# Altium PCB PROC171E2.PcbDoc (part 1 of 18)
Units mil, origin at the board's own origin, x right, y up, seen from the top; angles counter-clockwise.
Board outline 7700 x 2300 mil, 6 copper layers (Top Layer, GND 1, SIG 1, SIG 2, GND 2, Bottom Layer), stack 61.062 mil thick; 937 components, 687 nets, 11931 pads, 1719 vias.
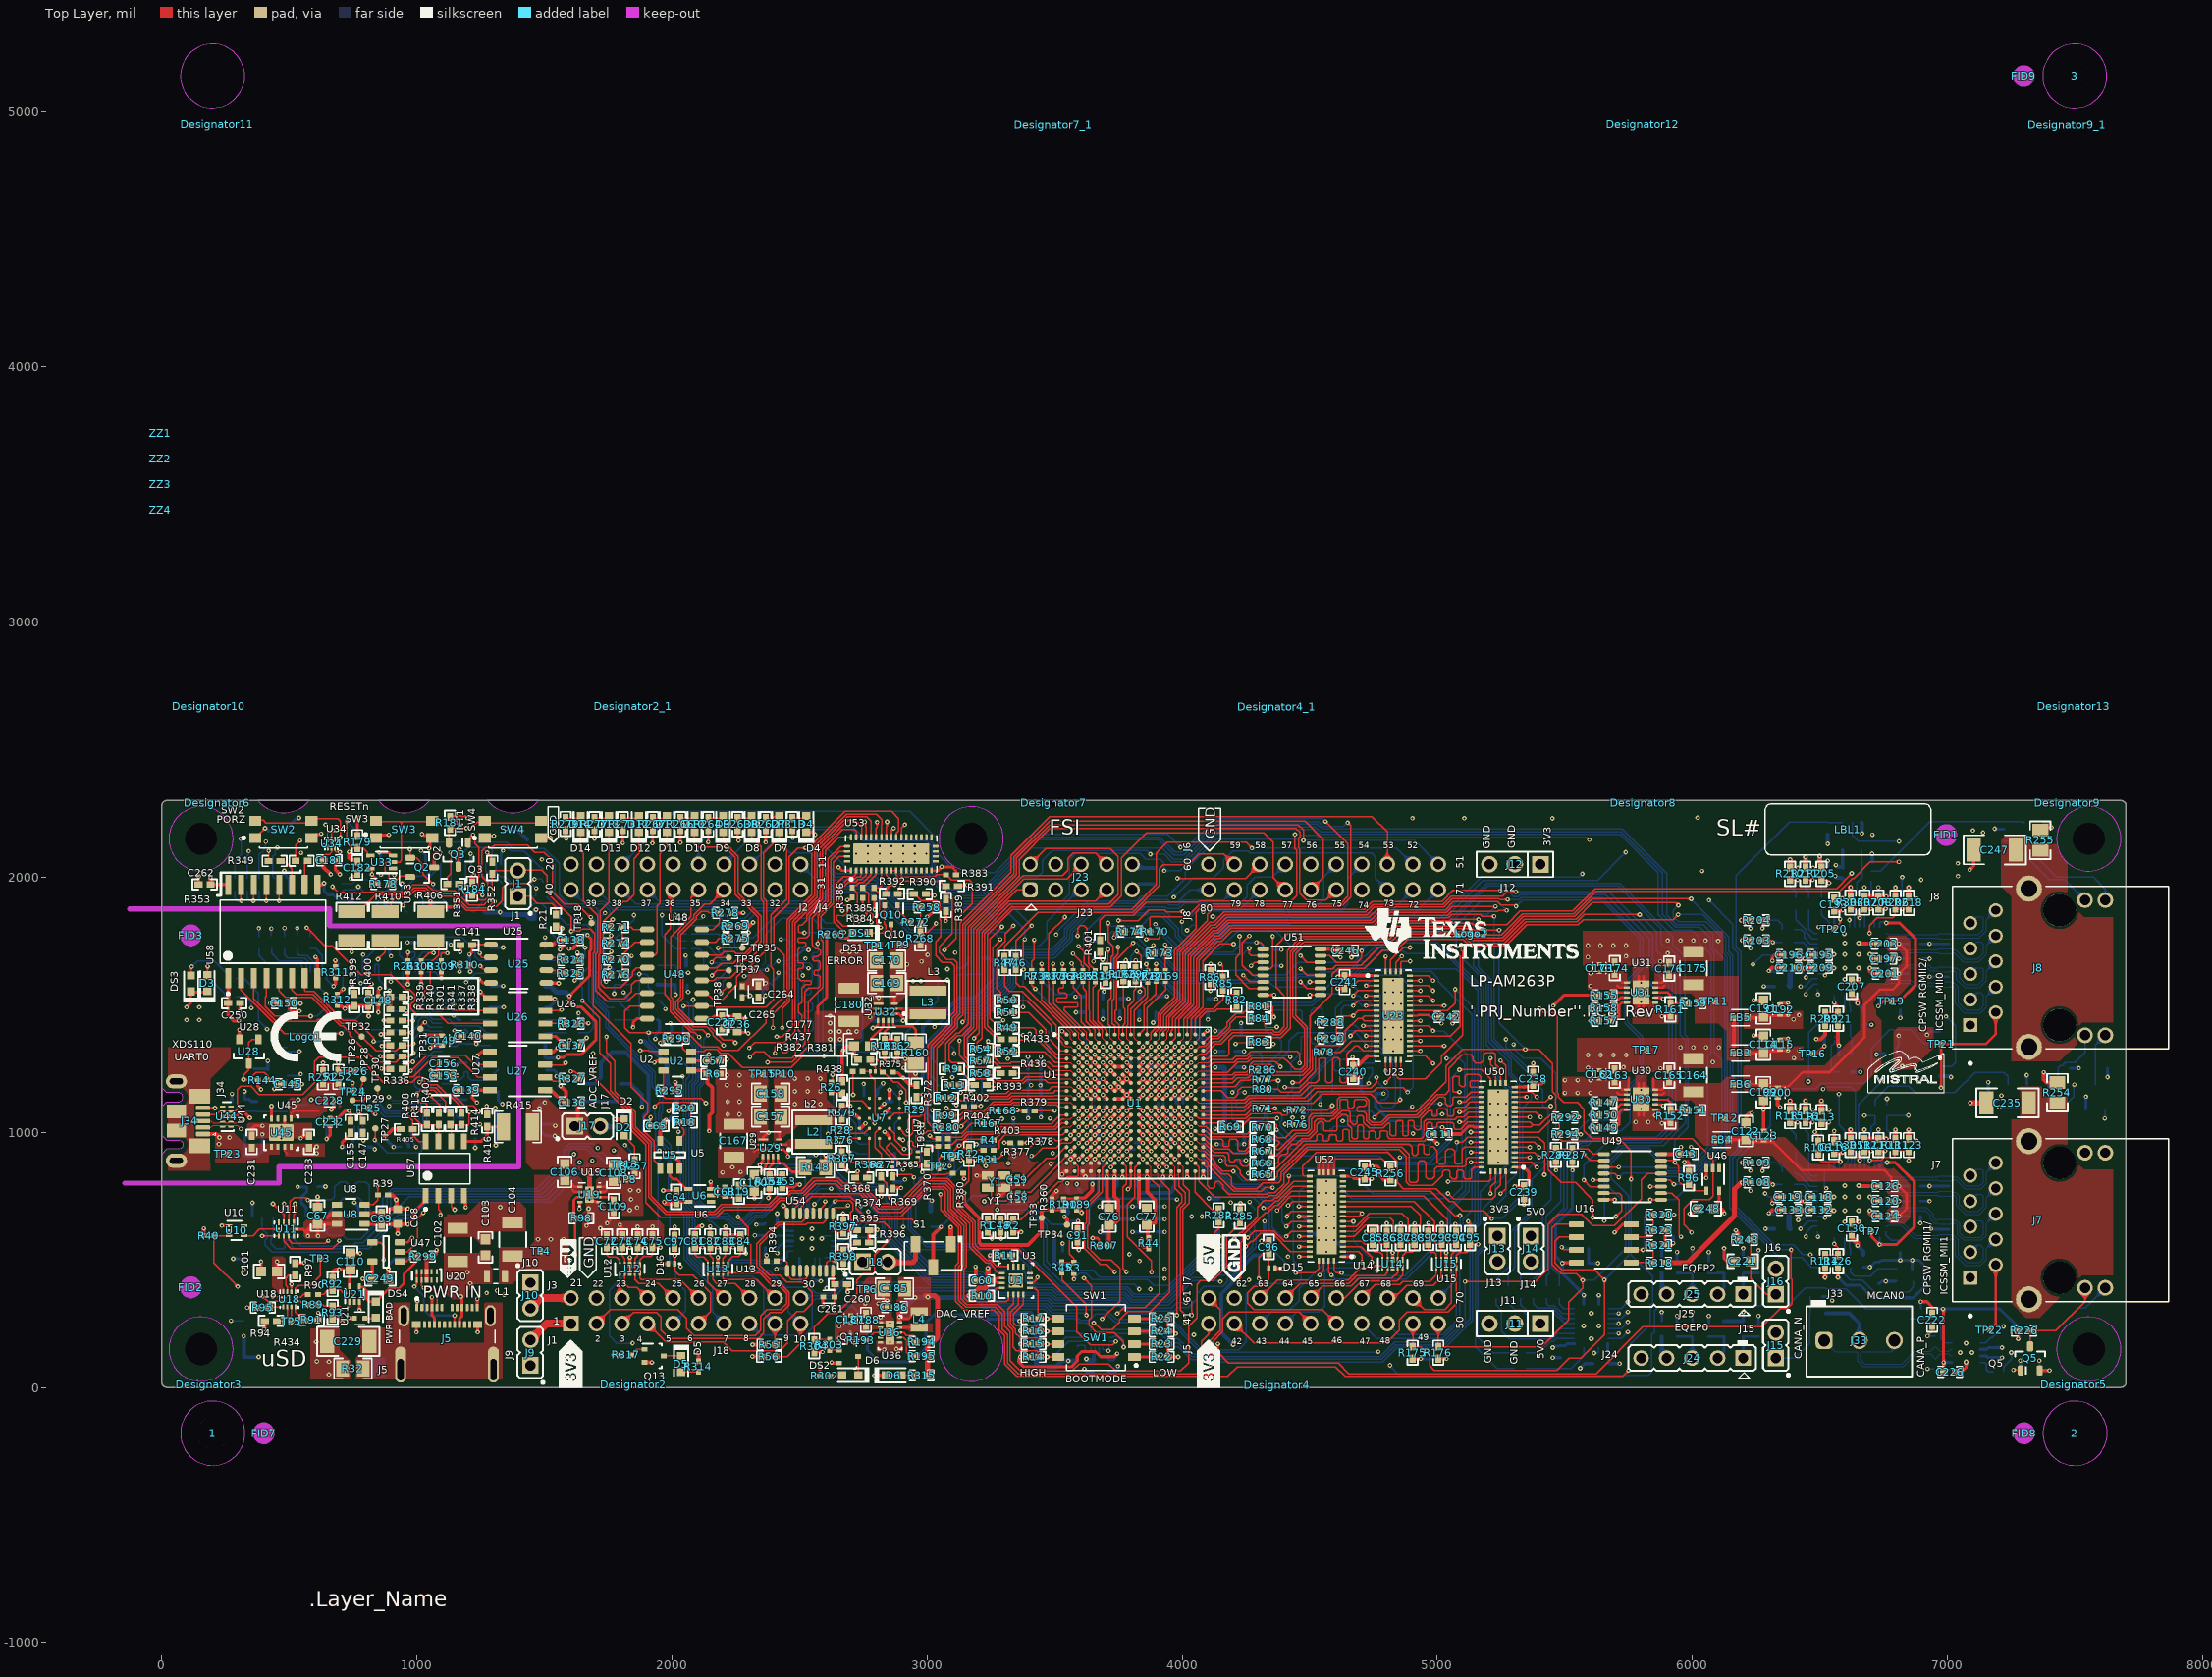
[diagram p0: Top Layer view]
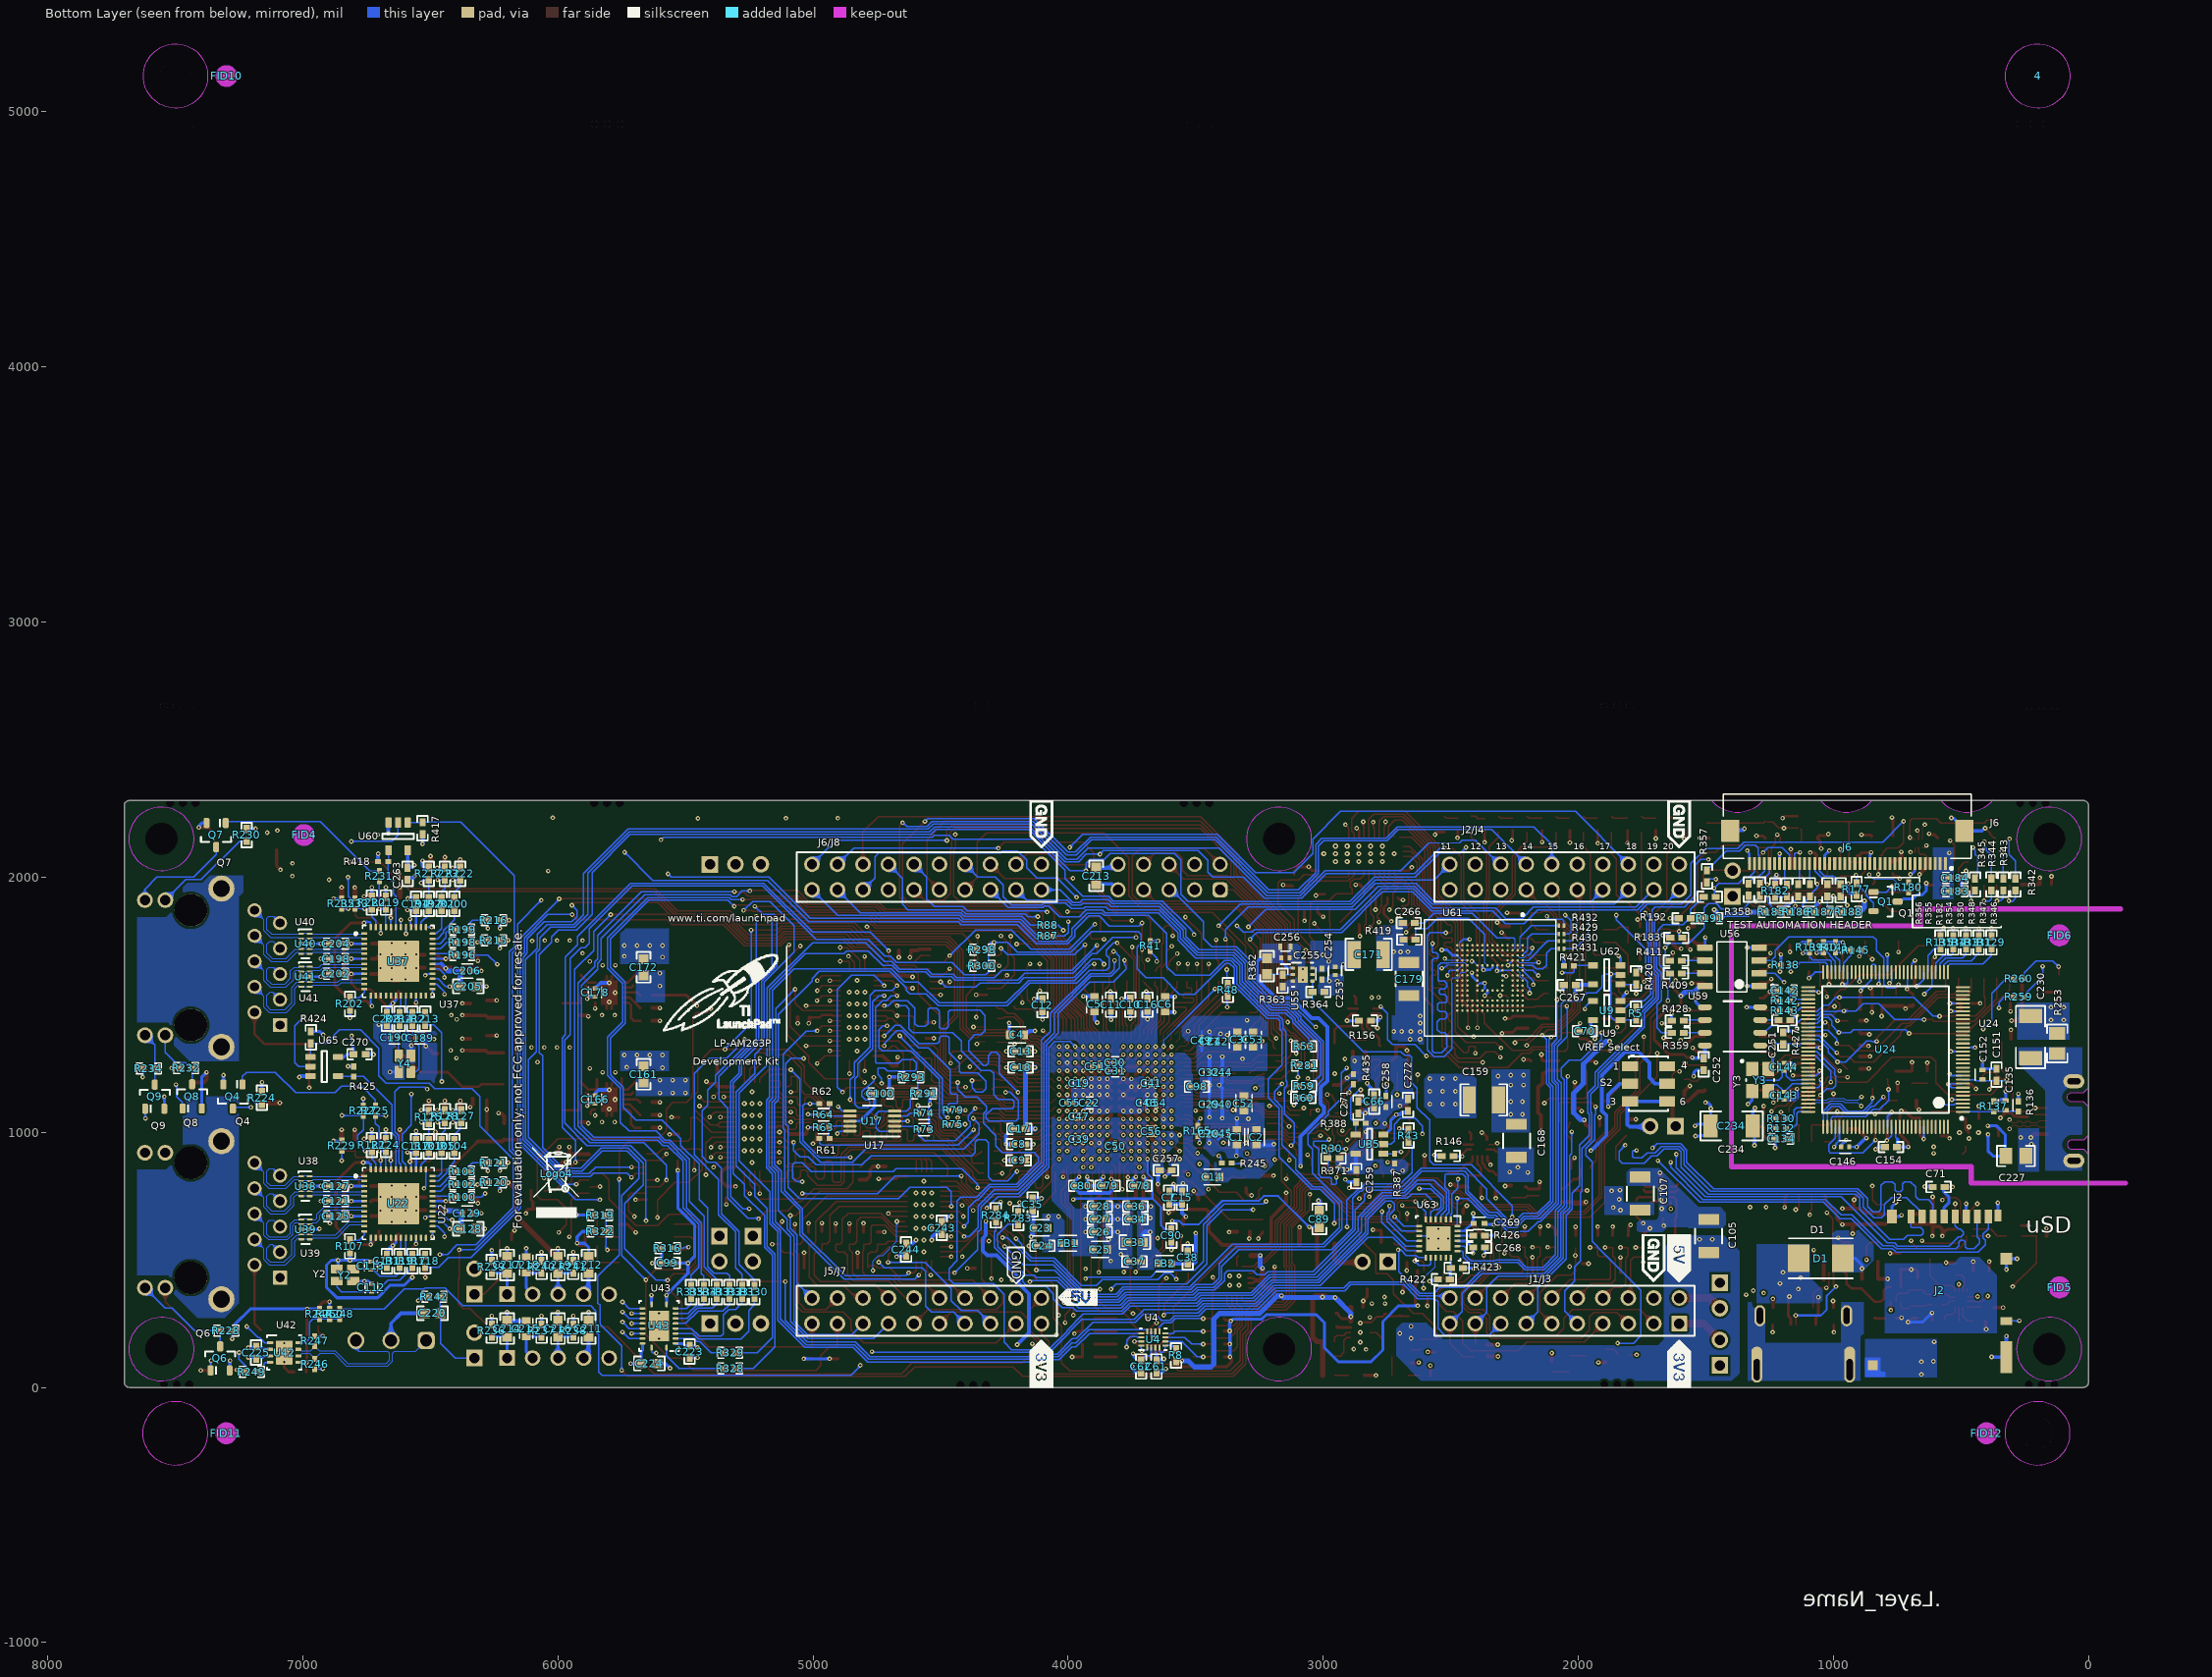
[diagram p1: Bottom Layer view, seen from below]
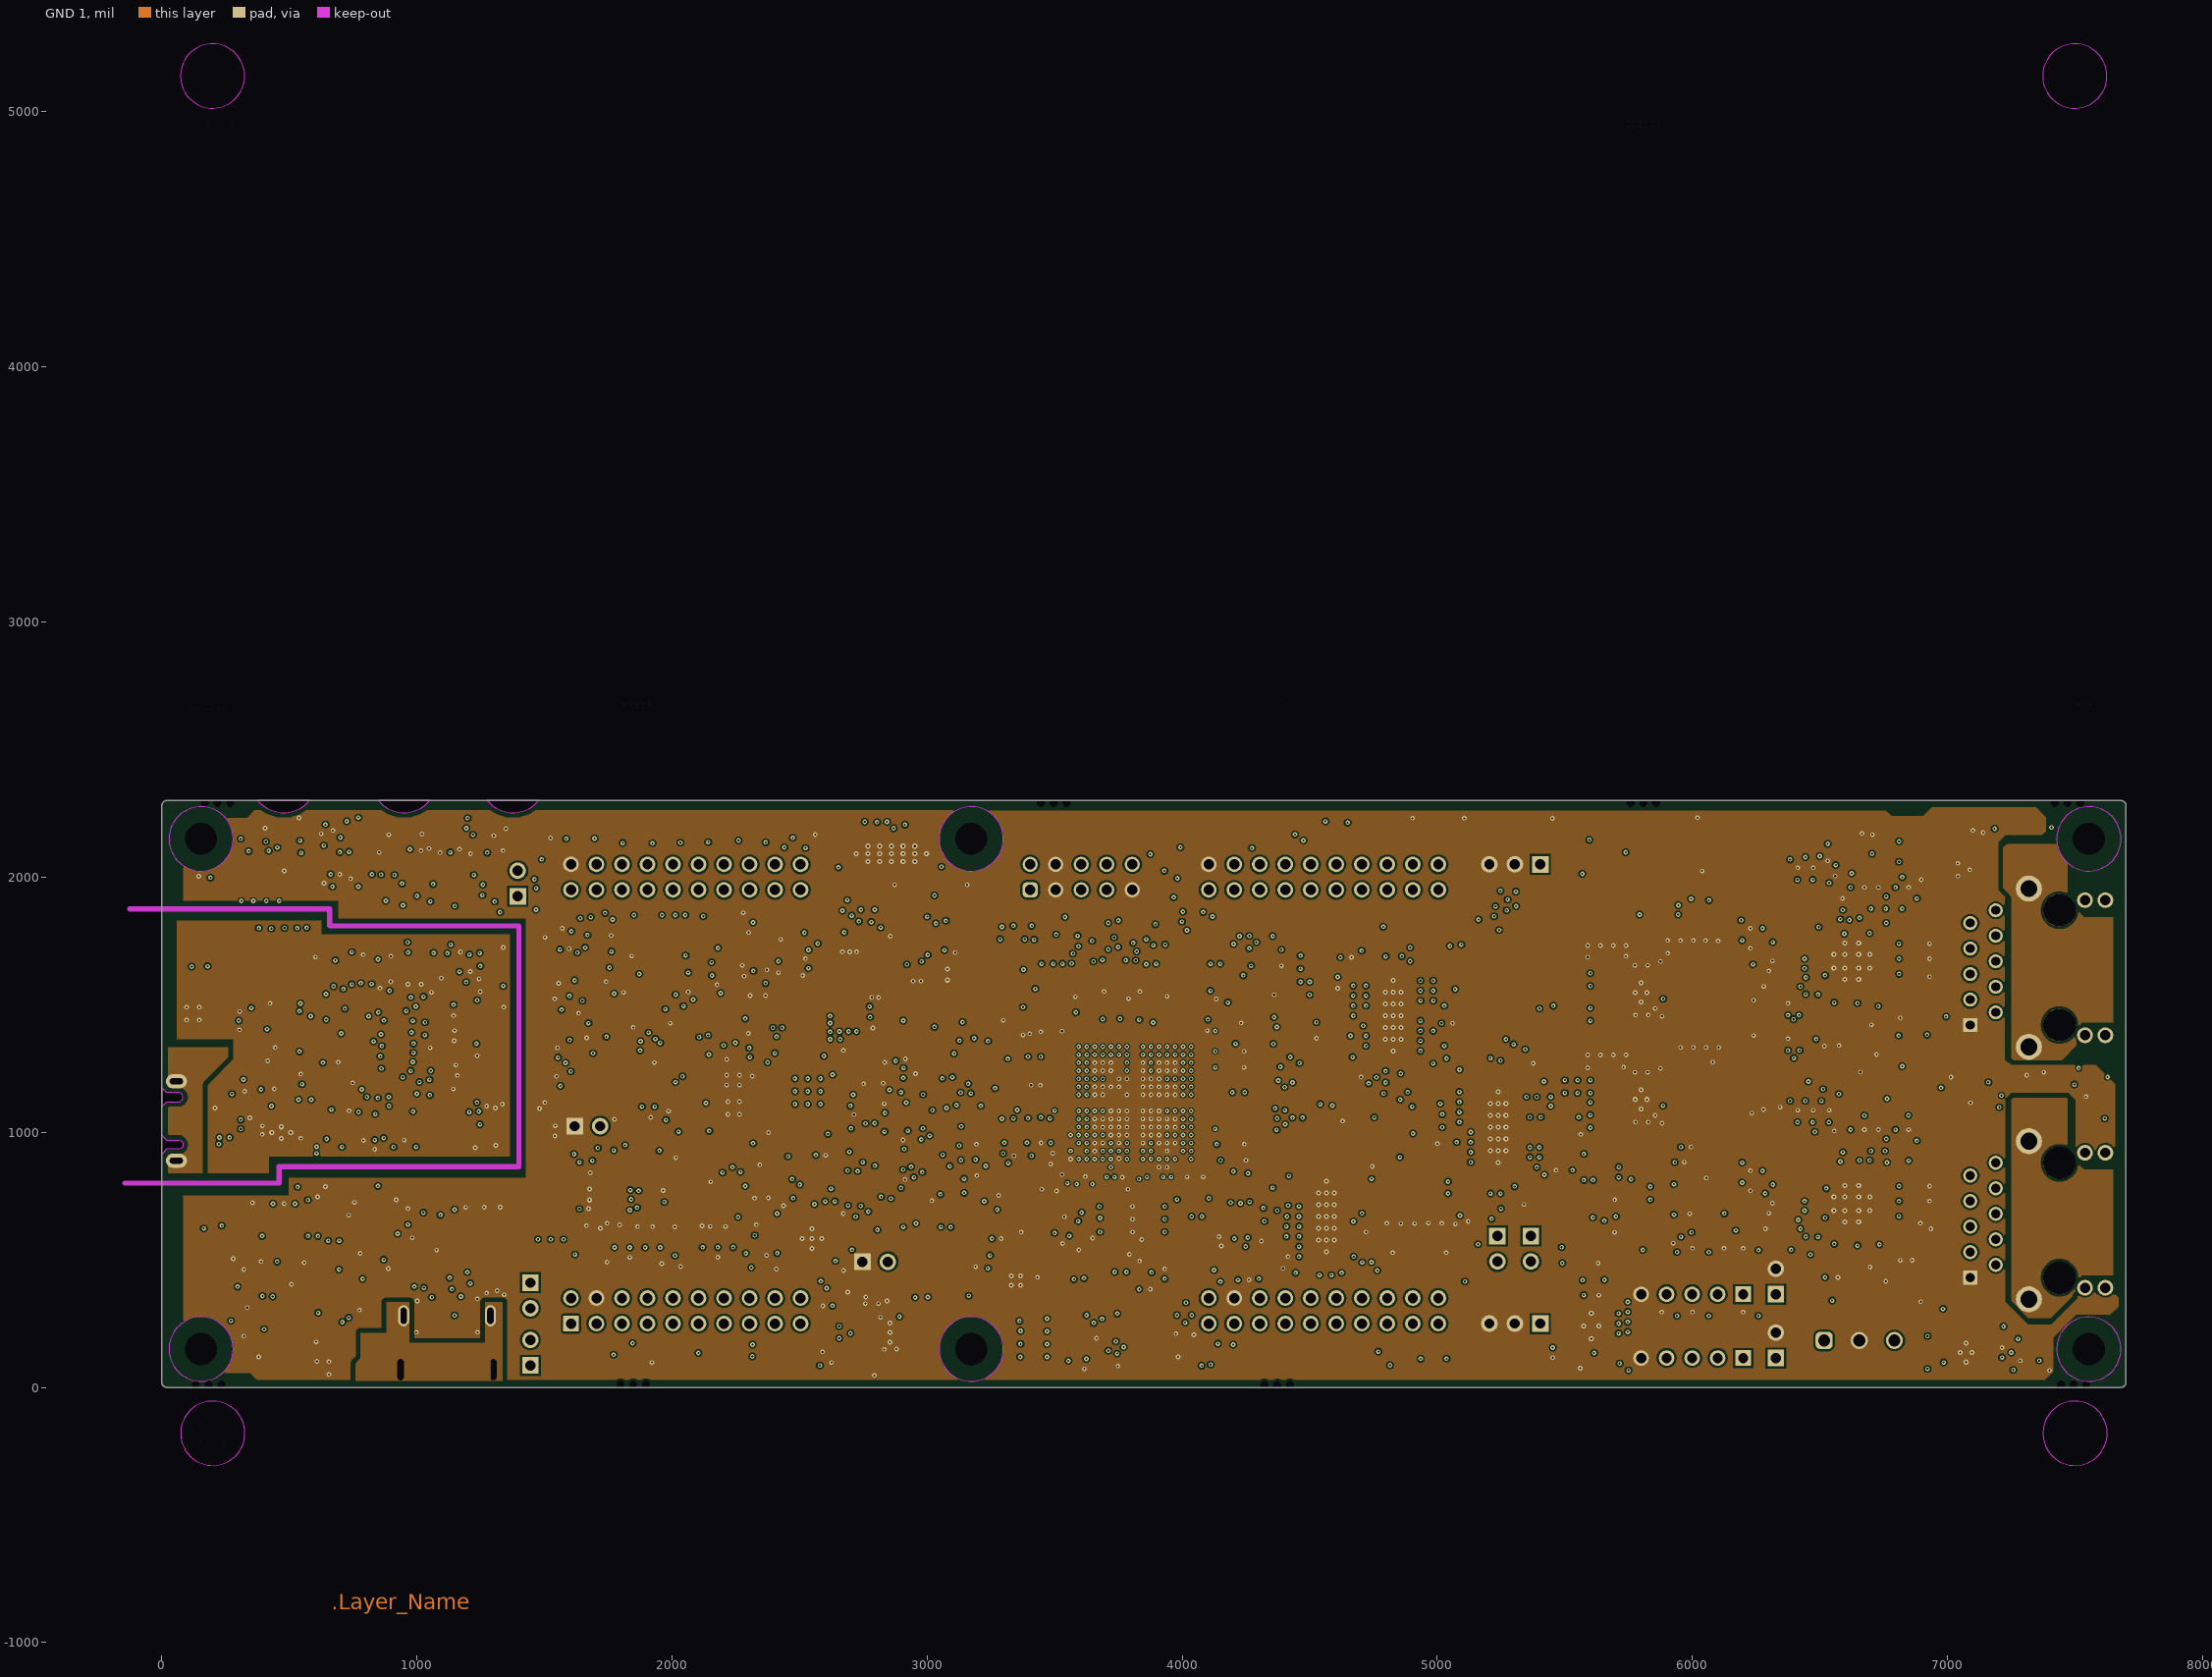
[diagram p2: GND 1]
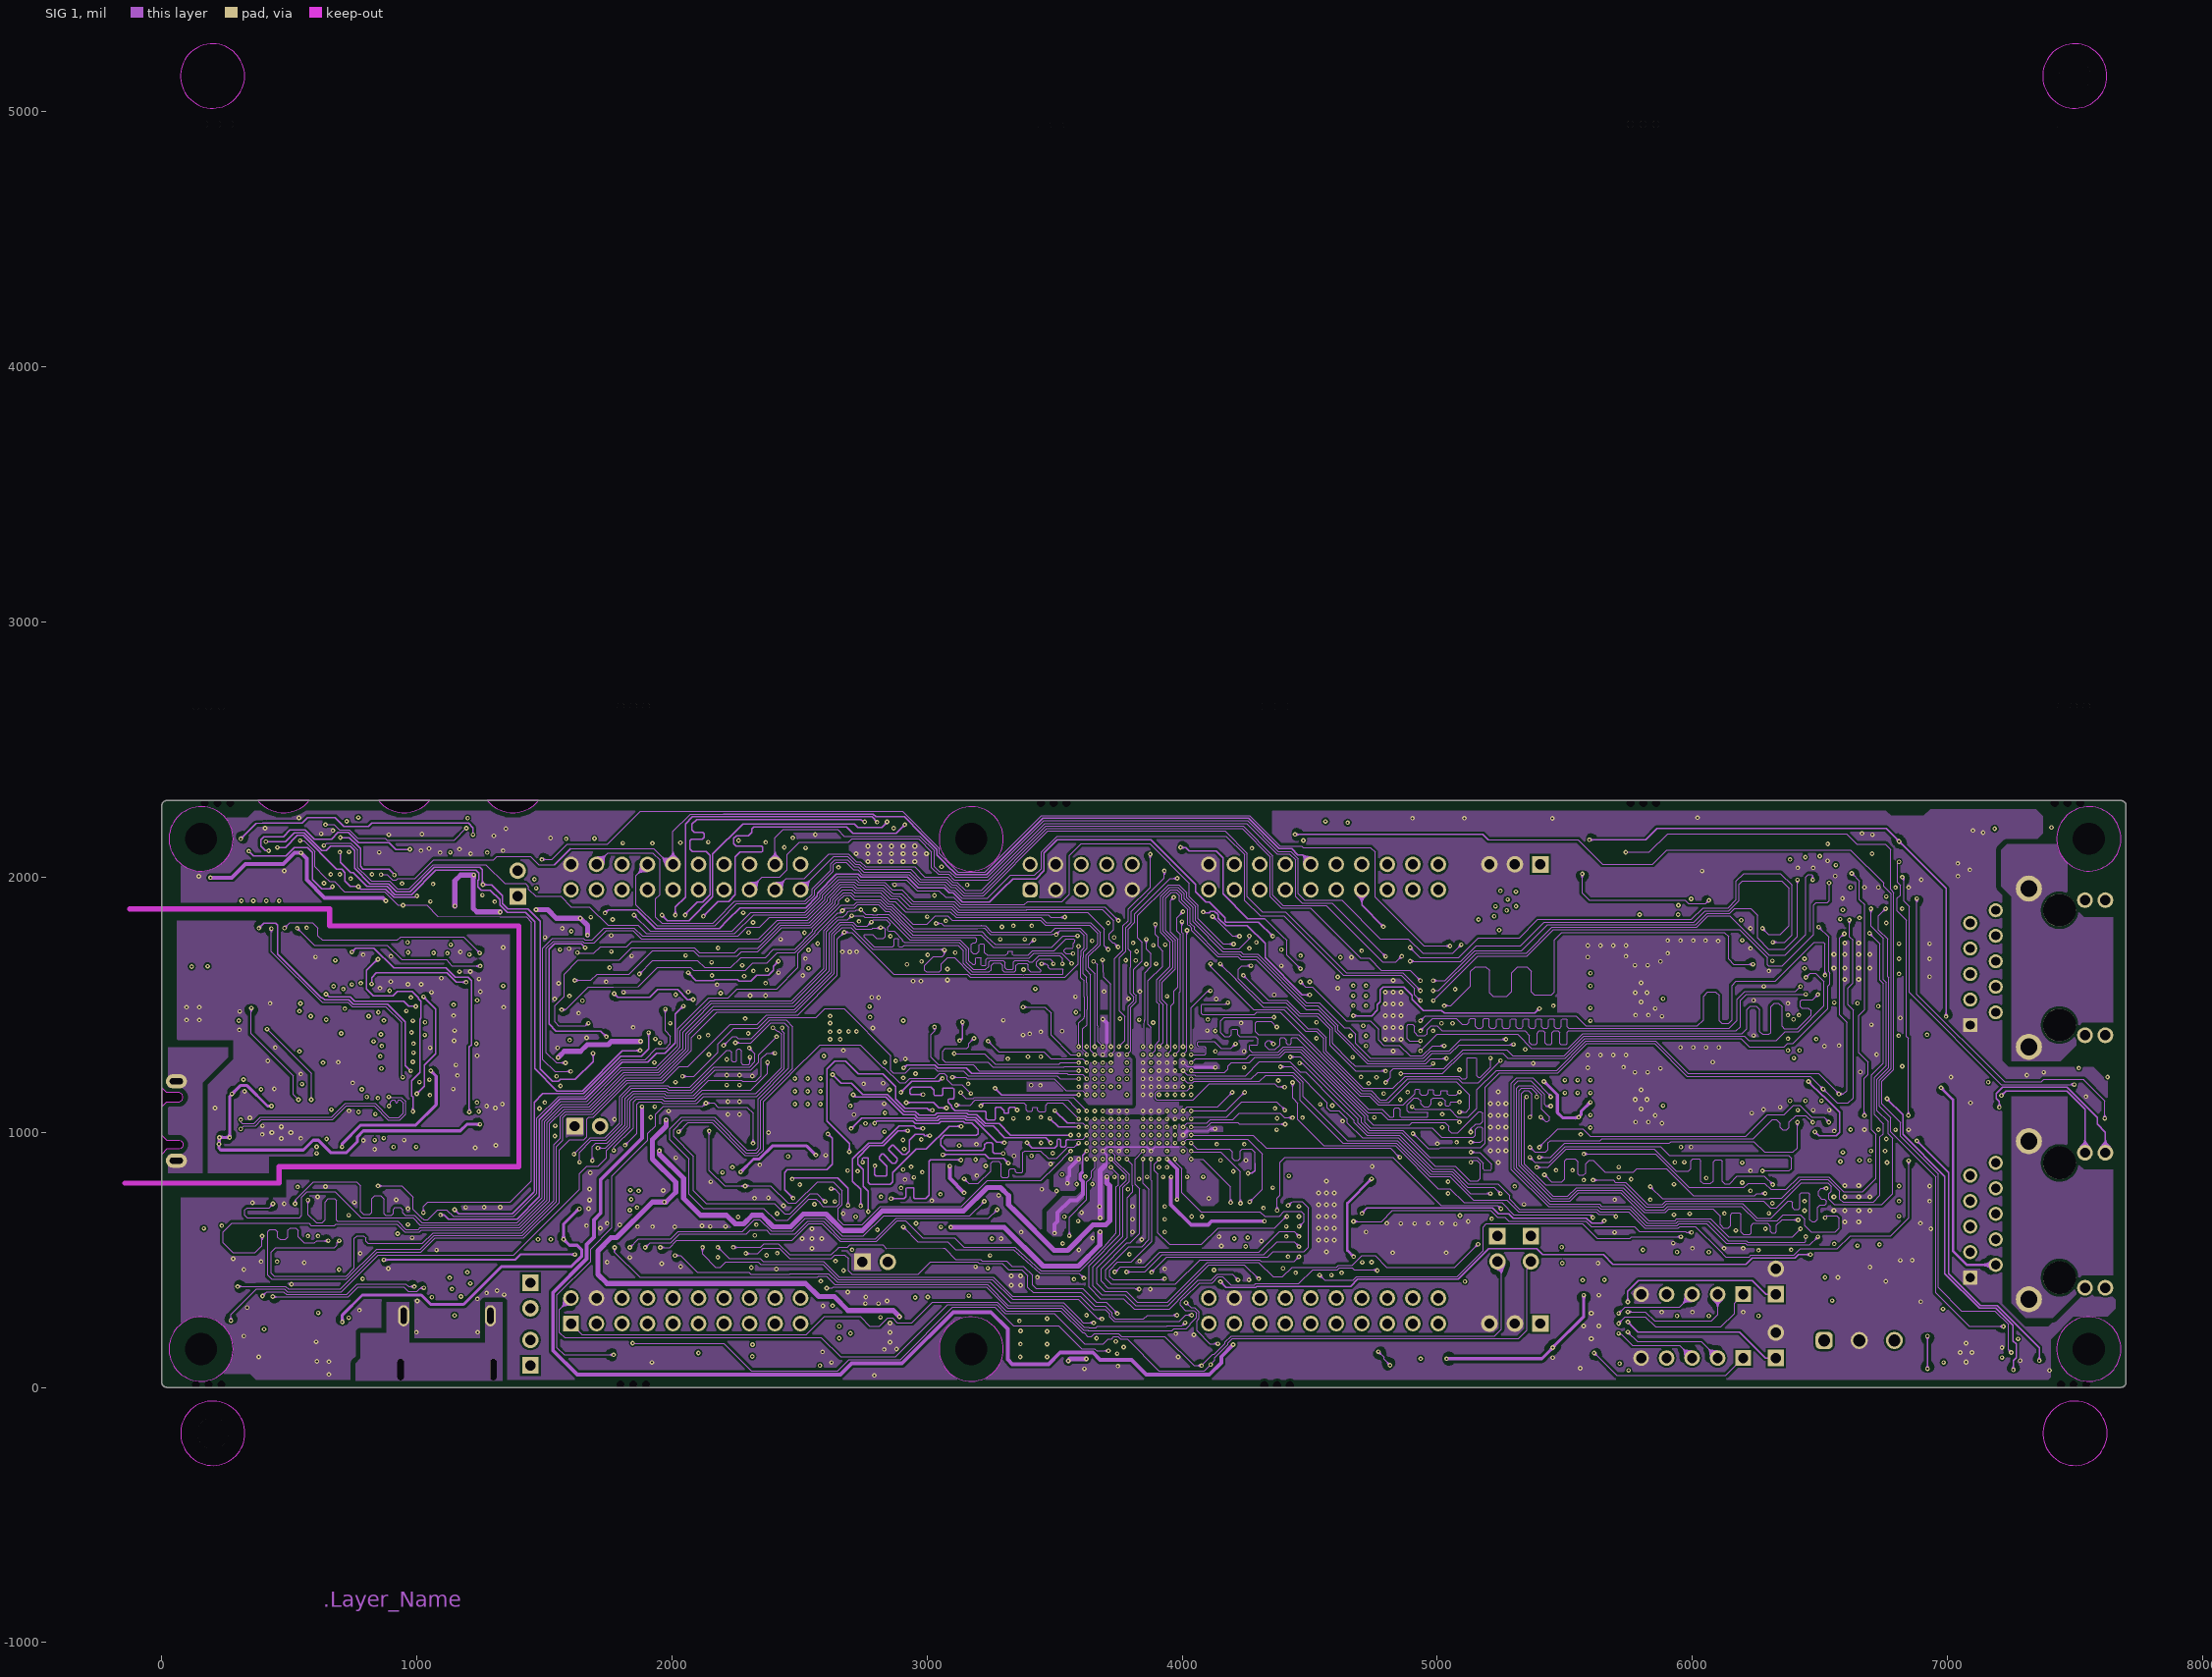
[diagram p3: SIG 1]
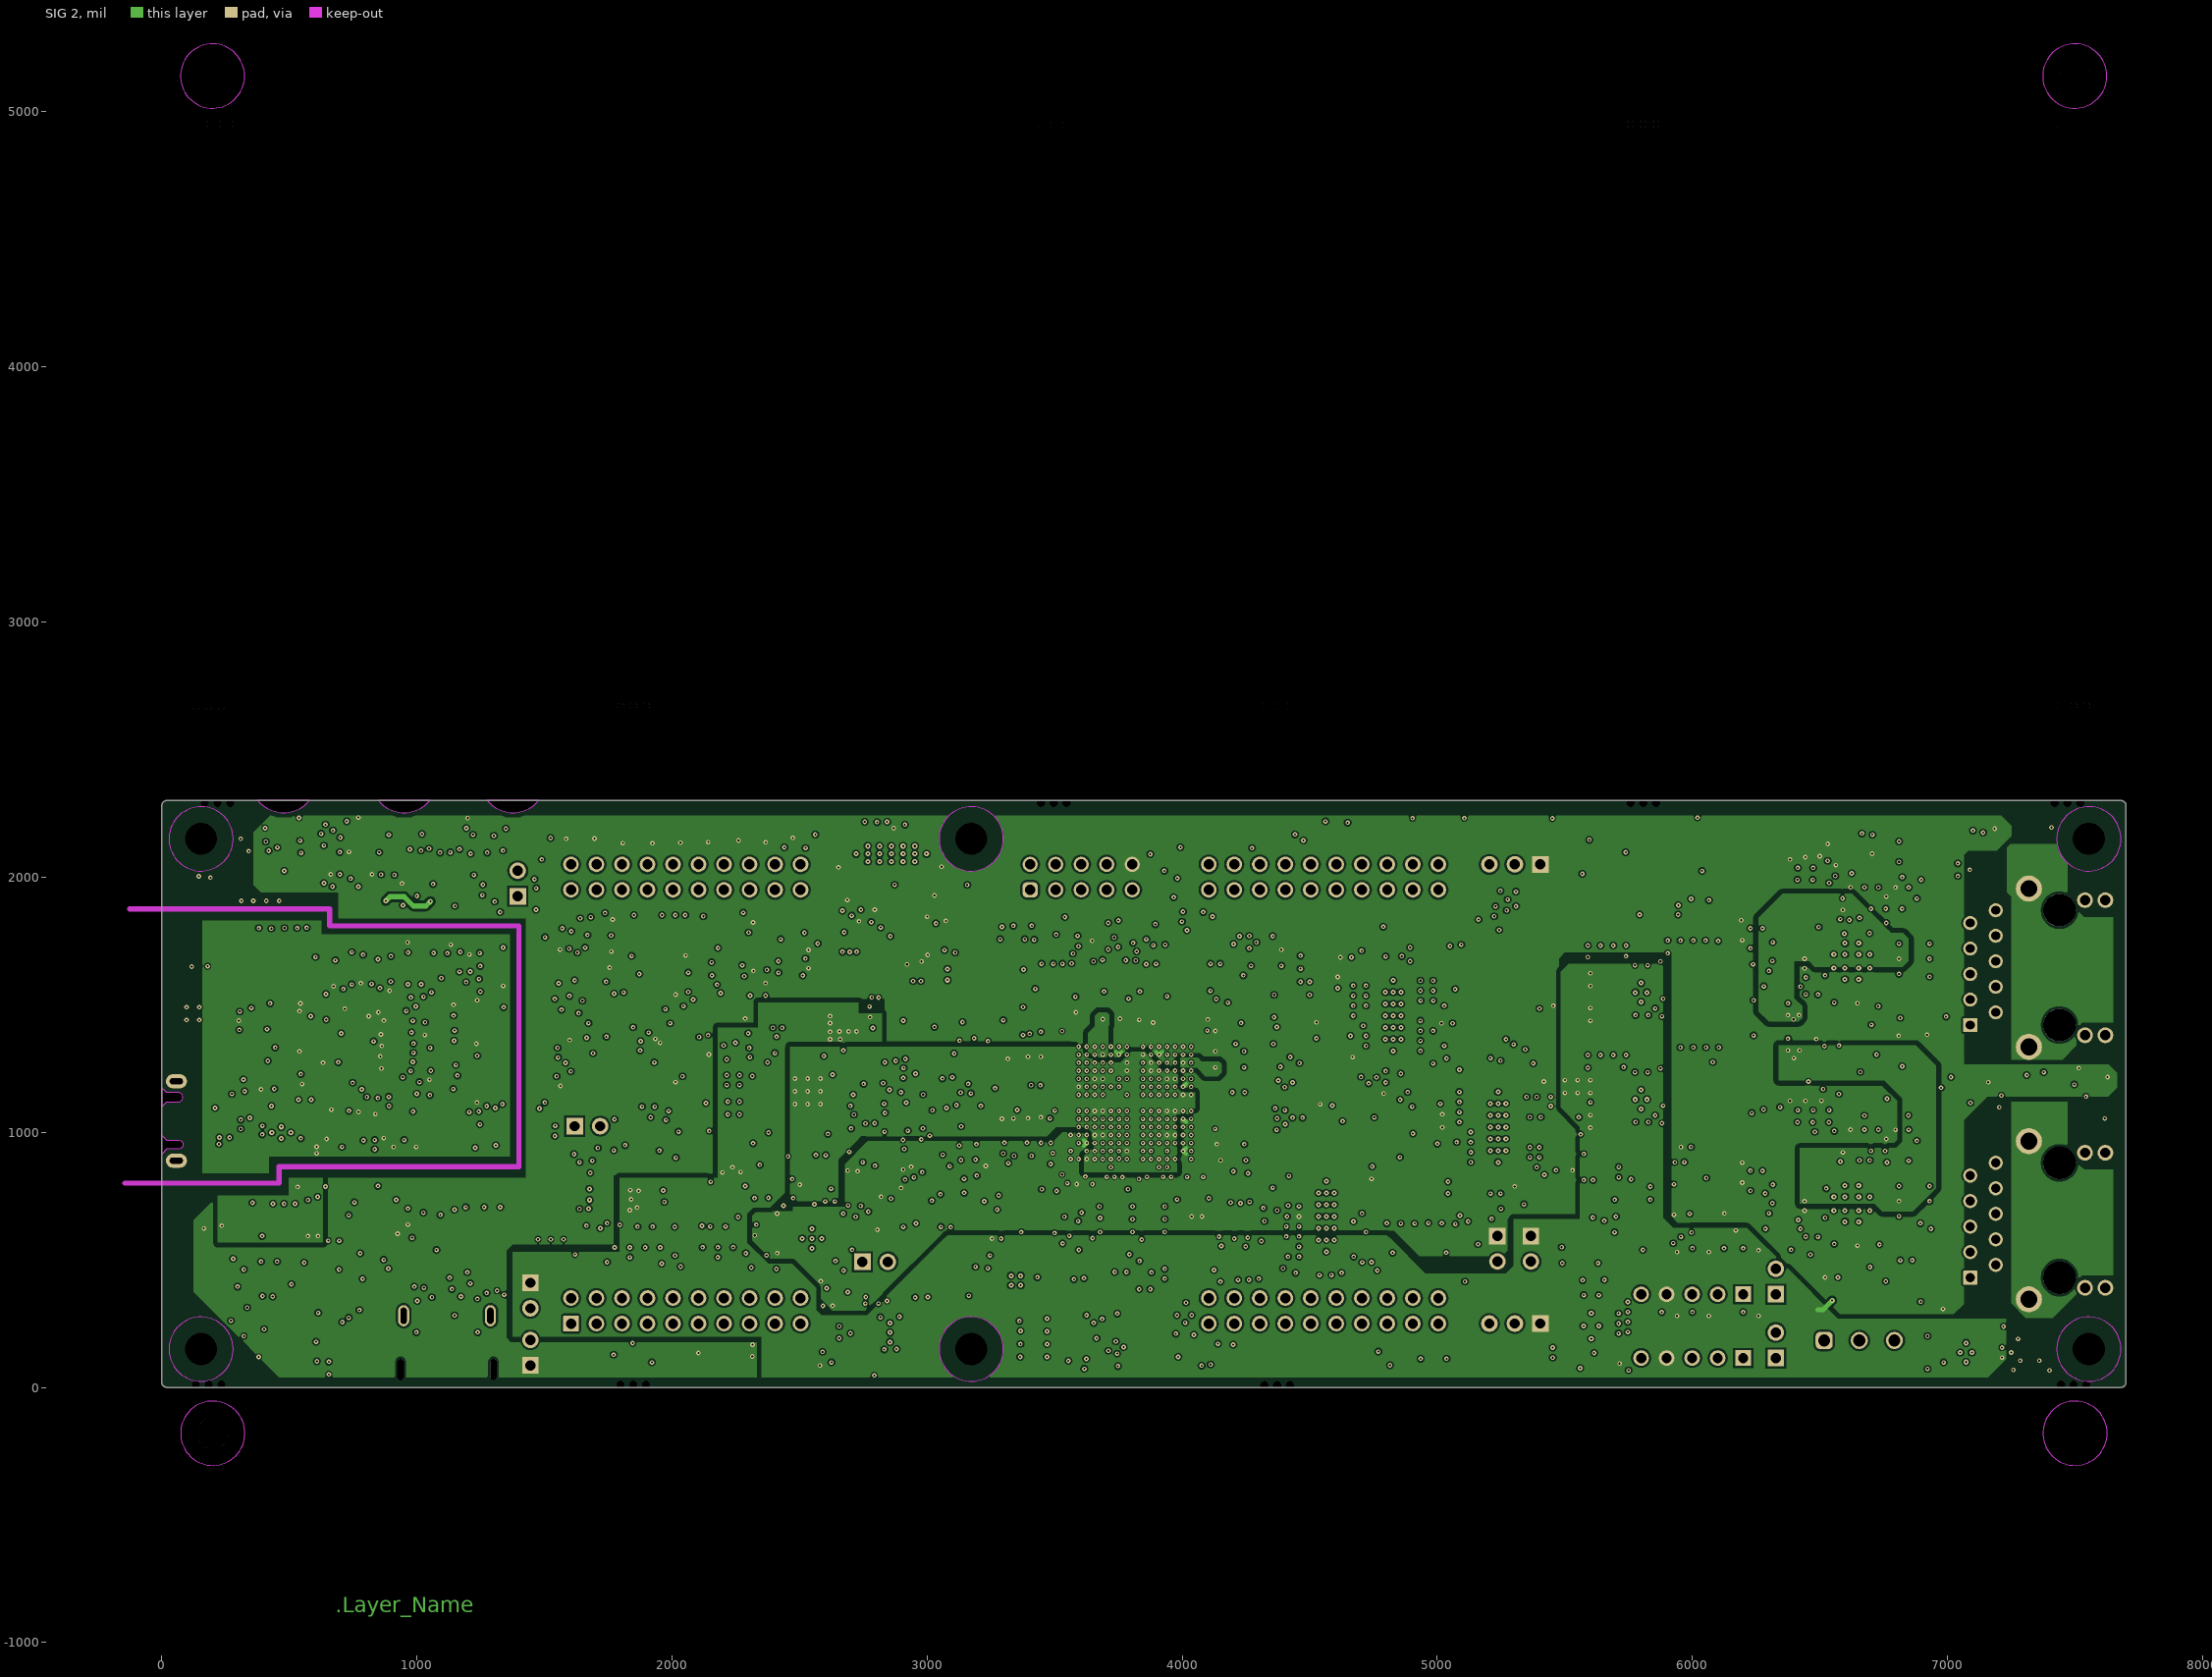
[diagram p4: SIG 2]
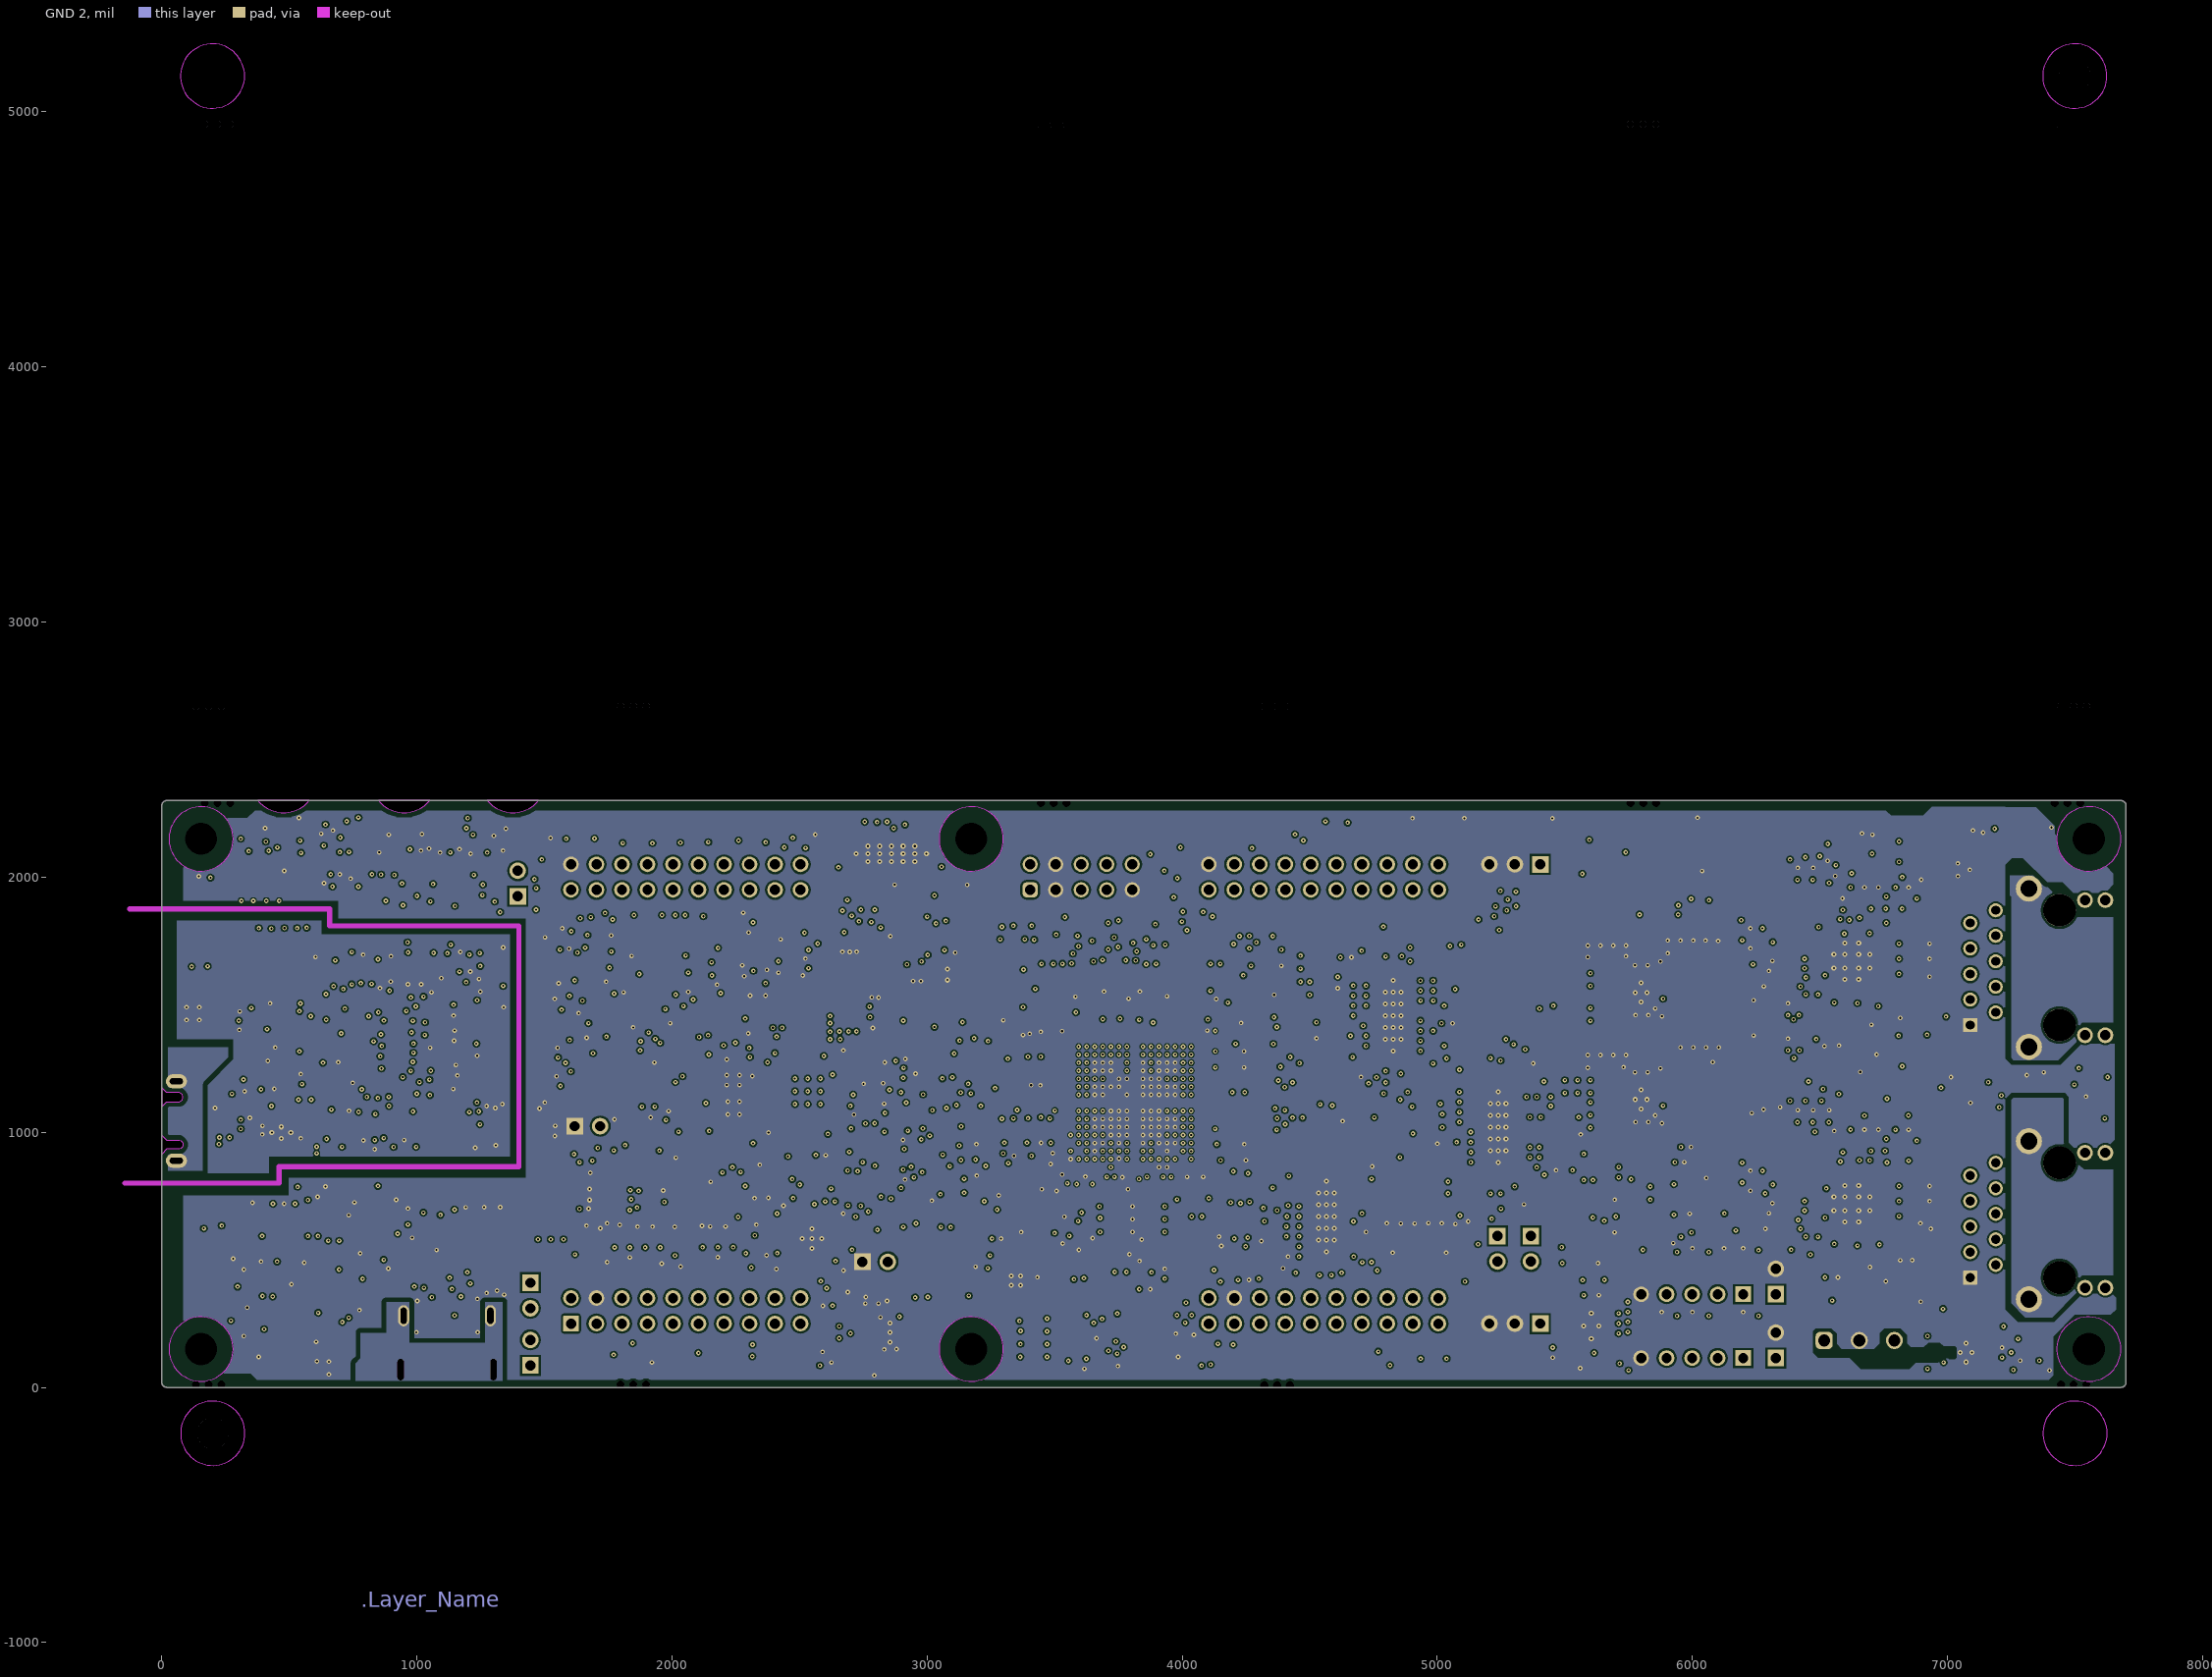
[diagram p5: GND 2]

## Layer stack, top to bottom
Top Solder: solder mask 1, Taiyo PSR 4000 HFX DI-GREEN, Dk 3.5
Top Layer: signal copper 2.087
Dielectric 1: prepreg 3.511, Iteq IT180A Prepreg 2113 RC58, Dk 4.13
GND 1: signal copper 1.26
Dielectric 3: core 4, Iteq IT180A 4 mil core 1/1, Dk 4.4
SIG 1: signal copper 1.26
Dielectric 5: core 1.75, Composite dielectric, Dk 3.79
Dielectric 6: core 2.663, Composite dielectric, Dk 3.79
Dielectric1: core 28, Composite dielectric, Dk 3.79
Dielectric 7: core 2.663, Composite dielectric, Dk 3.79
Dielectric 8: core 1.75, Composite dielectric, Dk 3.79
SIG 2: signal copper 1.26
Dielectric 4: core 4, Iteq IT180A 4 mil core 1/1, Dk 4.4
GND 2: signal copper 1.26
Dielectric 2: prepreg 3.511, Iteq IT180A Prepreg 2113 RC58, Dk 4.13
Bottom Layer: signal copper 2.087
Bottom Solder: solder mask 1, Taiyo PSR 4000 HFX DI-GREEN, Dk 3.5

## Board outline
0,20 0,2280 cw(c20,2280) 20,2300 7680,2300 cw(c7680,2280) 7700,2280 7700,20 cw(c7680,20) 7680,0 20,0 cw(c20,20)
cut-out: 377.6,2300 383.73,2292.69 397.98,2280.01 413.92,2269.53 431.21,2261.47 449.48,2256 468.35,2253.23 487.43,2253.23 506.3,2256 524.58,2261.47 541.86,2269.53 557.8,2280.01 572.05,2292.69 578.18,2300
cut-out: 1276.54,2300.05 1282.66,2292.76 1296.89,2280.09 1312.81,2269.62 1330.08,2261.57 1348.34,2256.1 1367.19,2253.34 1386.24,2253.34 1405.1,2256.1 1423.35,2261.57 1440.62,2269.62 1456.54,2280.09 1470.77,2292.76 1476.9,2300.05
cut-out: 849.83,2300 855.95,2292.71 870.17,2280.05 886.08,2269.59 903.33,2261.54 921.57,2256.08 940.41,2253.32 959.45,2253.32 978.29,2256.08 996.52,2261.54 1013.78,2269.59 1029.69,2280.05 1043.91,2292.71 1050.03,2300
cut-out: 0,913.66 0,988.47 19.68,968.78 64.96,968.78 68.48,968.78 75,966.08 79.98,961.1 82.68,954.59 82.68,947.54 79.98,941.03 75,936.05 68.48,933.35 64.96,933.35 19.68,933.35
cut-out: 0,1100.18 19.68,1119.86 64.96,1119.86 68.48,1119.86 75,1122.56 79.98,1127.54 82.68,1134.06 82.68,1141.1 79.98,1147.62 75,1152.6 68.48,1155.3 64.96,1155.3 19.68,1155.3 0,1174.98

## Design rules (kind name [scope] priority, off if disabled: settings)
AssemblyTestPointUsage [All] p1: valid=2
BoardOutlineClearance BoardOutlineClearance_MountingHoles [OnCopper and InComponentClass('Mounting Holes')] p1: gap=39.37 ignorepadtopadclearanceinfootprint=FALSE
BoardOutlineClearance BoardOutlineClearance_Poly [OnCopper and IsPoly] p2: gap=25 ignorepadtopadclearanceinfootprint=FALSE
BoardOutlineClearance [OnCopper and Not InComponentClass('Logo') and not InComponentClass('FiducialMark') and not InRegion(1000,500,4000,800) and not InPoly] p3: gap=40 ignorepadtopadclearanceinfootprint=FALSE
Clearance FLASH-4mil [WithinRoom('FLASH - NAND') and OnBottomLayer] p1: gap=3 ignorepadtopadclearanceinfootprint=TRUE except(3.4: Arc-SMDPad Track-SMDPad; 15: Fill-Fill Fill-Poly Fill-Region Poly-Poly Poly-Region Region-Region)
Clearance Clearance_Keepouts [IsKeepOut] p2: gap=1 ignorepadtopadclearanceinfootprint=FALSE
Clearance 4mil [WithinRoom('PROC111_Hardware')] p3: gap=4 ignorepadtopadclearanceinfootprint=TRUE except(15: Fill-Fill Fill-Poly Fill-Region Poly-Poly Poly-Region Region-Region)
Clearance ADC_EXT [(OnLayer('Top Layer') or OnLayer('Bottom Layer')) vs InNetClass('ADC0')] p4: gap=7.87 ignorepadtopadclearanceinfootprint=TRUE except(6: Via-Fill Via-Poly Via-Region; 10.6: Arc-Arc Arc-Track Track-Track; 18: Via-Via; 25: Fill-Fill Fill-Poly Fill-Region Poly-Poly Poly-Region Region-Region)
Clearance ADC_SIG1 [OnLayer('SIG 1') vs InNetClass('ADC0')] p5: gap=7.87 ignorepadtopadclearanceinfootprint=TRUE except(6: Via-Fill Via-Poly Via-Region; 9.5: Arc-Arc Arc-Track Track-Track; 18: Via-Via; 25: Fill-Fill Fill-Poly Fill-Region Poly-Poly Poly-Region Region-Region)
Clearance 100E_CLR_same [InDifferentialPairClass('100E')] p6: gap=7.87 ignorepadtopadclearanceinfootprint=TRUE except(7.7: Arc-Arc Arc-Track Track-Track; 10: Via-Fill Via-Poly Via-Region; 18: Via-Via; 25: Fill-Fill Fill-Poly Fill-Region Poly-Poly Poly-Region Region-Region)
Clearance 100E_CLR [InDifferentialPairClass('100E')] p7: gap=7.87 ignorepadtopadclearanceinfootprint=TRUE except(6: Via-Fill Via-Poly Via-Region; 16.2: Arc-Arc Arc-Track Track-Track; 18: Via-Via; 25: Fill-Fill Fill-Poly Fill-Region Poly-Poly Poly-Region Region-Region)
Clearance Clearance_Poly [InPolygon] p8: gap=10 ignorepadtopadclearanceinfootprint=TRUE except(6: Via-Fill Via-Poly Via-Region; 8: SMDPad-Fill SMDPad-Poly SMDPad-Region THPad-Fill THPad-Poly THPad-Region; 20: Fill-Fill Fill-Poly Fill-Region Poly-Poly Poly-Region Region-Region)
Clearance DIff_spacing [All vs InDifferentialPair('XDSET_1_D')] p9: gap=7.87 ignorepadtopadclearanceinfootprint=TRUE except(5: Arc-Arc Arc-Track Track-Track; 6: Via-Fill Via-Poly Via-Region; 18: Via-Via; 25: Fill-Fill Fill-Poly Fill-Region Poly-Poly Poly-Region Region-Region)
Clearance [All] p10: gap=7.87 ignorepadtopadclearanceinfootprint=TRUE except(5.3: Arc-Arc Arc-Track Track-Track; 6: SMDPad-SMDPad Via-Fill Via-Poly Via-Region; 7.4: Arc-SMDPad Track-SMDPad; 18: Via-Via; 25: Fill-Fill Fill-Poly Fill-Region Poly-Poly Poly-Region Region-Region)
ComponentClearance ComponentClearance_MountingHoles_FiducialMarks [InComponentClass('Mounting Holes') vs InComponentClass('FiducialMark')] p1: gap=50 collisioncheckmode=3 verticalgap=10 showdistances=FALSE
ComponentClearance ComponentClearance_Shunt [InComponentClass('Header') vs InComponentClass('Shunt')] p2: gap=0 collisioncheckmode=3 verticalgap=0 showdistances=FALSE
ComponentClearance ComponentClearance_Logo [InComponentClass('Logo')] p3: gap=30 collisioncheckmode=3 verticalgap=10 showdistances=FALSE
ComponentClearance ComponentClearance_ScrewToNut [(HasFootprint('NY PMS 440 0025 PH')) vs (HasFootprint('Keystone_1902C'))] p4: gap=5 collisioncheckmode=3 verticalgap=10 showdistances=FALSE
ComponentClearance ComponentClearance_MountingHoles [InComponentClass('Mounting Holes')] p5: gap=100 collisioncheckmode=3 verticalgap=100000 showdistances=FALSE
ComponentClearance ComponentClearance_SmallPassives [HasFootprint('0201*') or HasFootprint('0402*') or HasFootprint('0508') or HasFootprint('0603*') or HasFootprint('0612') or HasFootprint('0805*') or HasFootprint('0815*') or HasFootprint('0830*') or HasFootprint('1206*') or HasFootprint('1210*') or HasFootprint('1808*') or HasFootprint('1812*') or HasFootprint('1825*') or HasFootprint('2010*') or HasFootprint('2220*') or HasFootprint('2225*') or HasFootprint('2512*') or HasFootprint('2728*') or HasFootprint('3518*') vs HasFootprint('0201*') or HasFootprint('0402*') or HasFootprint('0508') or HasFootprint('0603*') or HasFootprint('0612') or HasFootprint('0805*') or HasFootprint('0815*') or HasFootprint('0830*') or HasFootprint('1206*') or HasFootprint('1210*') or HasFootprint('1808*') or HasFootprint('1812*') or HasFootprint('1825*') or HasFootprint('2010*') or HasFootprint('2220*') or HasFootprint('2225*') or HasFootprint('2512*') or HasFootprint('2728*') or HasFootprint('3518*')] p6: gap=10 collisioncheckmode=3 verticalgap=10 showdistances=FALSE
ComponentClearance ComponentClearance_THtoSMT [IsThruComponent vs IsSMTComponent] p7: gap=30 collisioncheckmode=3 verticalgap=30 showdistances=FALSE
ComponentClearance ComponentClearance_THtoTH [IsThruComponent vs IsThruComponent] p8: gap=20 collisioncheckmode=3 verticalgap=30 showdistances=FALSE
ComponentClearance [All] p9: gap=15 collisioncheckmode=3 verticalgap=15 showdistances=TRUE
DiffPairsRouting 90E [InDifferentialPair('XDSET_1_D')] p1: maxlimit=10 minlimit=5 mostfreqgap=10 toplayer_prefgap=5 toplayer_minwidth=4.2 toplayer_maxwidth=15 toplayer_prefwidth=4.2 midlayer1_mingap=6 midlayer1_maxgap=6 midlayer1_prefgap=6 midlayer1_minwidth=4 midlayer1_maxwidth=4 midlayer1_prefwidth=4 midlayer2_mingap=10 midlayer2_minwidth=15 midlayer2_maxwidth=15 midlayer2_prefwidth=15 midlayer3_mingap=10 midlayer3_minwidth=15 midlayer3_maxwidth=15 midlayer3_prefwidth=15 midlayer4_mingap=10 midlayer4_minwidth=15 midlayer4_maxwidth=15 midlayer4_prefwidth=15 bottomlayer_prefgap=5 bottomlayer_minwidth=4.2 bottomlayer_maxwidth=15 bottomlayer_prefwidth=4.2 maxuncoupledlength=500
DiffPairsRouting 120E [InDifferentialPair('CANA')] p2: maxlimit=10 minlimit=6.8 mostfreqgap=10 toplayer_prefgap=6.8 toplayer_minwidth=4.1 toplayer_maxwidth=15 toplayer_prefwidth=4.1 midlayer1_mingap=10 midlayer1_minwidth=15 midlayer1_maxwidth=15 midlayer1_prefwidth=15 midlayer2_mingap=10 midlayer2_minwidth=15 midlayer2_maxwidth=15 midlayer2_prefwidth=15 midlayer3_mingap=10 midlayer3_minwidth=15 midlayer3_maxwidth=15 midlayer3_prefwidth=15 midlayer4_mingap=10 midlayer4_minwidth=15 midlayer4_maxwidth=15 midlayer4_prefwidth=15 bottomlayer_prefgap=6.8 bottomlayer_minwidth=4.1 bottomlayer_maxwidth=15 bottomlayer_prefwidth=4.1 maxuncoupledlength=500
DiffPairsRouting 100E_DIFF [InDifferentialPairClass('100E')] p3: maxlimit=100 minlimit=7.7 mostfreqgap=10 toplayer_maxgap=7.7 toplayer_prefgap=7.7 toplayer_minwidth=4 toplayer_maxwidth=4 toplayer_prefwidth=4 midlayer1_mingap=8.1 midlayer1_maxgap=8.1 midlayer1_prefgap=8.1 midlayer1_minwidth=3.5 midlayer1_maxwidth=3.5 midlayer1_prefwidth=3.5 midlayer2_mingap=10 midlayer2_minwidth=15 midlayer2_maxwidth=15 midlayer2_prefwidth=15 midlayer3_mingap=10 midlayer3_minwidth=15 midlayer3_maxwidth=15 midlayer3_prefwidth=15 midlayer4_mingap=10 midlayer4_minwidth=15 midlayer4_maxwidth=15 midlayer4_prefwidth=15 bottomlayer_maxgap=7.7 bottomlayer_prefgap=7.7 bottomlayer_minwidth=4 bottomlayer_maxwidth=4 bottomlayer_prefwidth=4 maxuncoupledlength=1000
FabricationTestPointUsage TestPointUsage [All] p1: valid=2 allowmultiple=FALSE
FabricationTestpoint Testpoint [All] p1: side=3 testpointundercomponent=TRUE minsize=40 maxsize=100 preferedsize=60 minholesize=0 maxholesize=40 preferedholesize=32 testpointgrid=1 allowsidetop=TRUE allowsidebottom=TRUE usegrid=TRUE gridtolerance=0.01
FanoutControl Fanout_LCC [IsLCC] p1: bgadir=Out bgaviamode=Centered fanoutstyle=Auto fanoutdirection=Alternating viagrid=1 // Fanout_LCC (Default Rule)
FanoutControl Fanout_BGA [IsBGA] p2: bgadir=Out bgaviamode=Centered fanoutstyle=Auto fanoutdirection=Alternating viagrid=1 // Fanout_BGA (Default Rule)
FanoutControl Fanout_Default [All] p4: bgadir=Out bgaviamode=Centered fanoutstyle=Auto fanoutdirection=Alternating viagrid=1 // Fanout_Default (Default Rule)
FanoutControl Fanout_Small [(CompPinCount < 5)] p5: bgadir=Out bgaviamode=Centered fanoutstyle=Auto fanoutdirection=OutThenIn viagrid=1 // Fanout_Small (Default Rule)
HoleSize [All] p1: absolutevalues=TRUE maxlimit=251 minlimit=7.87 maxpercent=80.000 minpercent=20.000
MatchedLengths DIFF [All] p1: tolerance=2 checknetsindiffpair=TRUE checkdiffpairvsdiffpair=FALSE checkxsignals=FALSE checkothers=FALSE
MatchedLengths QSPI [InxSignalClass('QSPI_FLASH')] p2: tolerance=25 checknetsindiffpair=FALSE checkdiffpairvsdiffpair=TRUE checkxsignals=TRUE checkothers=TRUE
MatchedLengths ETH1_RX [InxSignalClass('ETH1_RX')] p3: tolerance=7.5 checknetsindiffpair=FALSE checkdiffpairvsdiffpair=TRUE checkxsignals=TRUE checkothers=TRUE
MatchedLengths ETH1_TX [InxSignalClass('ETH1_TX')] p4: tolerance=7.5 checknetsindiffpair=FALSE checkdiffpairvsdiffpair=TRUE checkxsignals=TRUE checkothers=TRUE
MatchedLengths ICSSM_MII0_RX [InxSignalClass('ICSSM_MII0_RX')] p5: tolerance=7.5 checknetsindiffpair=FALSE checkdiffpairvsdiffpair=TRUE checkxsignals=TRUE checkothers=TRUE
MatchedLengths AM263_RGMII1_TX [InxSignalClass('AM263_RGMII1_TX')] p6: tolerance=7.5 checknetsindiffpair=FALSE checkdiffpairvsdiffpair=TRUE checkxsignals=TRUE checkothers=TRUE
MatchedLengths PRO_PROU_GPIO(0-6) [InxSignalClass('PRO_PROU_GPIO(0-6)')] p7: tolerance=7.5 checknetsindiffpair=FALSE checkdiffpairvsdiffpair=TRUE checkxsignals=TRUE checkothers=TRUE
MatchedLengths PRO_PROU_GPIO(11-16) [InxSignalClass('PRO_PROU_GPIO(11-16)')] p8: tolerance=7.5 checknetsindiffpair=FALSE checkdiffpairvsdiffpair=TRUE checkxsignals=TRUE checkothers=TRUE
MatchedLengths AM263_RGMII1_RX [InxSignalClass('AM263_RGMII1_RX')] p9: tolerance=7.5 checknetsindiffpair=FALSE checkdiffpairvsdiffpair=TRUE checkxsignals=TRUE checkothers=TRUE
MatchedLengths ICSSM_MII0_TX [InxSignalClass('ICSSM_MII0_TX')] p10: tolerance=7.5 checknetsindiffpair=FALSE checkdiffpairvsdiffpair=TRUE checkxsignals=TRUE checkothers=TRUE
MatchedLengths ICSSM_MII1_TX [InxSignalClass('ICSSM_MII1_TX')] p11: tolerance=7.5 checknetsindiffpair=FALSE checkdiffpairvsdiffpair=TRUE checkxsignals=TRUE checkothers=TRUE
MatchedLengths ICSSM_MII1_RX [InxSignalClass('ICSSM_MII1_RX')] p12: tolerance=7.5 checknetsindiffpair=FALSE checkdiffpairvsdiffpair=TRUE checkxsignals=TRUE checkothers=TRUE
MatchedLengths "SD CARD" [InxSignalClass('MMC0')] p13: tolerance=25 checknetsindiffpair=FALSE checkdiffpairvsdiffpair=TRUE checkxsignals=TRUE checkothers=TRUE
MinimumAnnularRing MinimumAnnularRing_ThermalPadVias [IsVia and InAnyComponent] p1: minimumring=5.91
MinimumAnnularRing [All] p2: minimumring=5
MinimumSolderMaskSliver MinimumSolderMaskSliver_Logo [InComponentClass('Logo') vs InComponentClass('Logo')] p1: minsoldermaskwidth=0.7
PlaneConnect [All] p1: planeconnectstyle=Direct reliefexpansion=10 reliefentries=4 reliefconductorwidth=10 reliefairgap=10
PolygonConnect PolygonConnect_3 [All vs IsNamedPolygon('SIG 2-vusb_3v3')] p1: connectstyle=Direct reliefconductorwidth=10 reliefentries=4 polygonreliefangle="90 Angle" airgapwidth=10
PolygonConnect PolygonConnect_2 [All vs IsNamedPolygon('Top Layer-VBUS_TYPEC_5V0')] p2: connectstyle=Direct reliefconductorwidth=10 reliefentries=4 polygonreliefangle="90 Angle" airgapwidth=10
PolygonConnect PolygonConnect_1 [All vs IsNamedPolygon('Top Layer-VBUS_TYPEC_5V0')] p3: connectstyle=Direct reliefconductorwidth=10 reliefentries=4 polygonreliefangle="90 Angle" airgapwidth=10
PolygonConnect [All] p4: connectstyle=Direct reliefconductorwidth=10 reliefentries=4 polygonreliefangle="90 Angle" airgapwidth=10
RoomDefinition "FLASH - NAND" [False] p1: confinementstyle=ConfineIn formatcopy=TRUE lockcomponents=FALSE outline 2143.18,1838.8 2658.92,1838.8 2658.92,1382.11 2143.18,1382.11
RoomDefinition PROC111_Hardware [InComponentClass('PROC111_Hardware')] p2: confinementstyle=ConfineIn formatcopy=TRUE lockcomponents=FALSE outline 3491,782 4131,782 4131,1430 3491,1430
RoutingLayers [All] p1: top layer_v5=TRUE mid layer 1_v5=TRUE mid layer 2_v5=TRUE mid layer 3_v5=FALSE mid layer 4_v5=TRUE bottom layer_v5=TRUE
RoutingVias ThermalPadVias [IsVia and InAnyComponent] p1: holewidth=7.87 width=19.68 viastyle="Through Hole" minholewidth=7.87 minwidth=19.68 maxholewidth=12.99 maxwidth=23.62
RoutingVias [All] p2: holewidth=8 width=18 viastyle="Through Hole" minholewidth=8 minwidth=18 maxholewidth=8 maxwidth=18
SilkToBoardRegionClearance [Not ((IsComment or IsDesignator) And (Hide <> 'False')) and not InRegion(1000,500,4000,800)] p1:
SilkToSilkClearance SilkToSilkClearance_Pb-FreeLogo [(HasFootprint('Pb-Free_Overlay_Medium') OR HasFootprint('Pb-Free_Overlay_Small')) vs (HasFootprint('Pb-Free_Overlay_Medium') OR HasFootprint('Pb-Free_Overlay_Small'))] p1: silktosilkclearance=0
SilkToSilkClearance [All] p2: silktosilkclearance=3.94
SilkToSolderMaskClearance SilkToComponentPadClearance [(IsPad or IsFill or IsRegion) and Component] p1: minsilkscreentomaskgap=3.54 clearancetoexposedcopper=TRUE
SilkToSolderMaskClearance "Silk to Solder Mask Opening" [All] p2: minsilkscreentomaskgap=3 clearancetoexposedcopper=FALSE
SolderMaskExpansion [All] p1: expansion=1.97 istentingtop=FALSE
UnRoutedNet [All] p1: checkbadconnections=TRUE
Width 4mil_soc [WithinRoom('PROC111_Hardware')] p1: maxlimit=20 minlimit=4 preferedwidth=15 toplayer_prefwidth=4 midlayer1_prefwidth=4 midlayer3_minwidth=10 midlayer3_maxwidth=10 midlayer3_prefwidth=10 midlayer4_minwidth=10 midlayer4_maxwidth=10 midlayer4_prefwidth=10 bottomlayer_prefwidth=4 minimp=50.000000 maximp=50.000000 favimp=50.000000
Width "4 mil_mux" [WithinRoom('FLASH - NAND')] p2: maxlimit=15 minlimit=3.4 preferedwidth=10 toplayer_prefwidth=5.3 midlayer1_maxwidth=10 midlayer1_prefwidth=4.75 midlayer2_maxwidth=10 midlayer2_prefwidth=4.75 midlayer3_minwidth=5.3 midlayer3_maxwidth=10 midlayer4_minwidth=5.3 midlayer4_maxwidth=10 bottomlayer_prefwidth=5.3 minimp=50.000000 maximp=50.000000 favimp=50.000000
Width PWR [InNetClass('PWR')] p3: maxlimit=30 minlimit=6 preferedwidth=12 midlayer1_minwidth=8 midlayer2_minwidth=8 midlayer3_minwidth=8 midlayer4_minwidth=8 bottomlayer_minwidth=7 minimp=50.000000 maximp=50.000000 favimp=50.000000
Width [not WithinRoom('PROC111_Hardware')and WithinRoom('FLASH - NAND')] p4: maxlimit=100 minlimit=4.75 preferedwidth=5.3 toplayer_minwidth=5.3 midlayer1_prefwidth=4.75 midlayer2_minwidth=5.3 midlayer3_minwidth=5.3 midlayer4_minwidth=5.3 bottomlayer_minwidth=5.3 minimp=50.000000 maximp=50.000000 favimp=50.000000 checkconnectedcopper=TRUE
13 further rules are at their usual default settings.

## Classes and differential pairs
component class PROC171_IO_EXPANDER: C268 C269 R422 R423 R426 U63
component class PROC171_AM263P_4_EMMC: C264 C265 C266 C267 R419 R420 R421 R429 R430 R431 R432 TP35 TP36 TP37 TP38 U61 U62
net class POWER: VBUS_XDS_5V0
component class PROC171_XDS110_2: C134 C135 C136 C137 C138 C139 C140 C141 C142 C143 C144 C145 C146 C147 C148 C149 C150 C151 C152 C153 C154 C155 C156 C234 D3 DS3 R129 R130 R131 R132 R133 R134 R135 R136 R137 R138 R139 R140 R141 R142 R143 R144 R145 R259 R260 R261 R308 R309 R310 R311 R312 R324 R325 R326 R327 R399 R400 TP27 TP28 TP29 TP30 TP31 U24 U25 U26 U27 U28 Y3
component class PROC171_XDS110_1: C227 C228 C230 C231 C232 C233 J34 R251 R252 R253 TP23 TP24 TP25 TP26 U44 U45
component class PROC171_Test_Automation: C183 C184 C185 C186 C187 C188 C250 C251 C252 C262 J1 J6 L4 R21 R182 R183 R184 R185 R186 R187 R188 R191 R192 R193 R194 R195 R301 R336 R337 R338 R339 R340 R341 R342 R343 R344 R345 R346 R347 R348 R349 R350 R351 R352 R353 R354 R355 R356 R357 R358 R359 R405 R406 R407 R408 R409 R410 R411 R412 R413 R414 R415 R416 R427 R428 TP18 TP32 U36 U56 U57 U58 U59
component class PROC171_System_Power_2: C157 C158 C159 C160 C161 C162 C163 C164 C165 C166 C167 C168 C169 C170 C171 C172 C173 C174 C175 C176 C177 C178 C179 C180 C253 C254 C255 C256 L2 L3 R146 R147 R148 R149 R150 R151 R152 R153 R154 R155 R156 R157 R158 R159 R160 R161 R162 R163 R295 R296 R362 R363 R364 TP8 TP9 TP10 TP11 TP12 TP13 TP14 TP15 TP16 TP17 TP33 TP34 U29 U30 U31 U32 U55
component class PROC171_System_Power_1: C101 C102 C103 C104 C105 C106 C107 C108 C109 C110 C229 C249 D1 DS4 J5 J11 J12 L1 R32 R89 R90 R91 R92 R93 R94 R95 R97 R98 R299 R434 TP3 TP4 TP5 TP6 U18 U19 U20 U21 U47
component class PROC171_Push_Buttons: C181 C182 Q1 Q2 Q3 R177 R178 R179 R180 R181 SW2 SW3 SW4 U33 U34
component class PROC171_LED: C236 C237 D2 D4 D5 D6 D7 D8 D9 D10 D11 D12 D13 D14 DS1 DS2 Q10 Q11 Q13 R257 R262 R263 R264 R265 R266 R267 R268 R269 R270 R271 R272 R273 R274 R275 R276 R277 R278 R279 R302 R303 R304 R313 R314 R315 R317 U48
component class PROC171_Ehernet_RJ45_2: C247 J8 Q7 Q8 Q9 R230 R231 R232 R233 R234 R235 R255 TP22 U40 U41
component class PROC171_Ehernet_RJ45_1: C235 J7 Q4 Q5 Q6 R224 R225 R226 R227 R228 R229 R254 TP21 U38 U39
component class PROC171_Ehernet_PHY_2: C189 C190 C191 C192 C193 C194 C195 C196 C197 C198 C199 C200 C201 C202 C203 C204 C205 C206 C207 C208 C209 C210 C263 FB5 FB6 R196 R197 R198 R199 R200 R201 R202 R203 R204 R205 R206 R207 R208 R209 R210 R211 R212 R213 R214 R215 R216 R217 R218 R219 R220 R221 R222 R223 R306 R417 R418 TP19 TP20 U37 U60 Y4
component class PROC171_Ehernet_PHY_1: C112 C113 C114 C115 C116 C117 C118 C119 C120 C121 C122 C123 C124 C125 C126 C127 C128 C129 C130 C131 C132 C133 C240 C241 C242 C270 FB3 FB4 R100 R101 R102 R103 R104 R105 R106 R107 R108 R109 R110 R111 R112 R113 R114 R115 R116 R117 R118 R119 R120 R121 R122 R123 R124 R125 R126 R127 R128 R291 R292 R293 R294 R305 R424 R425 TP7 U22 U50 U65 Y2
component class PROC171_Breakout_Headers: C211 C212 C213 C214 C215 C216 C217 C218 C219 C220 C221 C222 C223 C224 C225 C226 J15 J16 J17 J18 J23 J24 J25 J33 R236 R237 R238 R239 R240 R241 R242 R243 R244 R246 R247 R248 R249 R250 R328 R329 R330 R331 R332 R333 R334 R335 U42 U43
component class PROC171_Boosterpack_Headers: C243 C244 C245 C246 J1/J3 J2/J4 J5/J7 J6/J8 J9 J10 J13 J14 R256 R298 R300 U51 U52
component class PROC171_AM263P_Serial_Connectivity: R164 R165 R166 R167 R168 R169 R170 R171 R172 R173 R174 R175 R176 R297 R401 R402 R403 R404
component class PROC171_AM263P_8_PRU: C43 C111 C238 C239 C248 R71 R72 R73 R74 R75 R76 R77 R78 R79 R80 R81 R82 R83 R84 R85 R86 R87 R88 R96 R286 R287 R288 R289 R290 U23 U46 U49
component class PROC171_AM263P_7_RGMII_MII: C100 R61 R62 R63 R64 R65 R66 R67 R68 R69 R70 U17
component class PROC171_AM263P_6_ePWM_eQEP_FSI: C260 C261 R9 R12 R13 R46 R47 R48 R49 R50 R51 R52 R53 R54 R55 R56 R57 R58 R59 R60 R99 R280 R281 R282 R283 R284 R285 R393 R394 R395 R396 R397 R398 R433 R436 U54
component class PROC171_AM263P_3_OSPI_MMC: C66 C67 C68 C69 C70 C71 C258 C259 C271 C272 J2 R26 R27 R28 R29 R30 R31 R33 R34 R35 R36 R37 R38 R39 R40 R41 R42 R43 R361 R365 R366 R367 R368 R369 R370 R371 R372 R373 R374 R375 R376 R377 R378 R379 R380 R381 R382 R383 R384 R385 R386 R387 R388 R389 R390 R391 R392 R435 R437 R438 U7 U8 U9 U10 U11 U35 U53
component class PROC171_AM263P_2_Clock_Reset_Boot_JTAG: C57 C58 C59 C60 C61 C62 C63 C64 C65 C99 R4 R5 R6 R7 R8 R10 R11 R14 R15 R16 R17 R18 R19 R20 R22 R23 R24 R25 R245 R258 R316 R318 R319 R320 R321 R322 R323 SW1 TP1 TP2 U2 U3 U4 U5 U6 U16 Y1
component class PROC171_AM263P_1_Power: C1 C2 C3 C4 C5 C6 C7 C8 C9 C10 C11 C12 C13 C14 C15 C16 C17 C18 C19 C20 C21 C22 C23 C24 C25 C26 C27 C28 C29 C30 C31 C32 C33 C34 C35 C36 C37 C38 C39 C40 C41 C42 C44 C45 C46 C47 C48 C49 C50 C51 C52 C53 C54 C55 C56 C98 C257 FB1 FB2 R1 R2 R189 R190 R360
component class PROC171_AM263P_5_ADC_DAC: C72 C73 C74 C75 C76 C77 C78 C79 C80 C81 C82 C83 C84 C85 C86 C87 C88 C89 C90 C91 C92 C93 C94 C95 C96 C97 D15 D16 R3 R44 R45 R307 S1 S2 U1 U12 U13 U14 U15
component class PROC171_Hardware: FID1 FID2 FID3 FID4 FID5 FID6 LBL1 Logo1 Logo2 Logo3 Logo4 ZZ1 ZZ2 ZZ3 ZZ4
differential pair XDSET_1_D: +XDSET_1_D_P -XDSET_1_D_N
differential pair ETH2_TD_D: +ETH2_TD_D_P -ETH2_TD_D_N
differential pair ETH2_TD_C: +ETH2_TD_C_P -ETH2_TD_C_N
differential pair ETH2_TD_B: +ETH2_TD_B_P -ETH2_TD_B_N
differential pair ETH2_TD_A: +ETH2_TD_A_P -ETH2_TD_A_N
differential pair ETH1_TD_D: +ETH1_TD_D_P -ETH1_TD_D_N
differential pair ETH1_TD_C: +ETH1_TD_C_P -ETH1_TD_C_N
differential pair ETH1_TD_B: +ETH1_TD_B_P -ETH1_TD_B_N
differential pair ETH1_TD_A: +ETH1_TD_A_P -ETH1_TD_A_N
differential pair CANA: +CANA_P -CANA_N

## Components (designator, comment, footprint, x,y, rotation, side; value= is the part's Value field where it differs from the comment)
1 "Comment" MHNP_M3_PANHEAD_PHILLIPS 200,-180 r0 top
2 "Comment" MHNP_M3_PANHEAD_PHILLIPS 7500,-180 r180 top
3 "Comment" MHNP_M3_PANHEAD_PHILLIPS 7499,5140 r180 top
4 "Comment" MHNP_M3_PANHEAD_PHILLIPS 199,5140 r0 bottom
C1 "CL10A335KP8NNNC" FP-CL10A335KP8NNNC_0603-MFG 3338.57,980.78 r270 bottom value=3.3µF
C2 "CL10A335KP8NNNC" FP-CL10A335KP8NNNC_0603-MFG 3262.14,980.78 r270 bottom value=3.3µF
C3 "CL10A335KP8NNNC" FP-CL10A335KP8NNNC_0603-MFG 3336.54,1363.15 r90 bottom value=3.3µF
C4 "CL10A335KP8NNNC" FP-CL10A335KP8NNNC_0603-MFG 4200,1381.81 r0 bottom value=3.3µF
C5 "CL10A335KP8NNNC" FP-CL10A335KP8NNNC_0603-MFG 3896.57,1501.5 r90 bottom value=3.3µF
C6 "CL10A335KP8NNNC" FP-CL10A335KP8NNNC_0603-MFG 3619.13,1501.5 r90 bottom value=3.3µF
C7 "GRM155R71E104KE14D" 0402 3603.63,743.75 r270 bottom value=0.1uF
C8 "GRM155R71E104KE14D" 0402 4192.18,952.97 r0 bottom value=0.1uF
C9 "GRM155R71E104KE14D" 0402 4193.67,890 r0 bottom value=0.1uF
C10 "GRM155R71E104KE14D" 0402 3756.08,1499.91 r90 bottom value=0.1uF
C11 "GRM155R71E104KE14D" 0402 3831.66,1499.91 r90 bottom value=0.1uF
C12 "GRM155R71E104KE14D" 0402 4100.67,1498.22 r90 bottom value=0.1uF
C13 "GRM155R71E104KE14D" 0402 4186.18,1317.07 r0 bottom value=0.1uF
C14 "CL10A335KP8NNNC" FP-CL10A335KP8NNNC_0603-MFG 3435,824.72 r180 bottom value=3.3µF
C15 "GRM155R71E104KE14D" 0402 3553.63,743.75 r270 bottom value=0.1uF
C16 "GRM155R71E104KE14D" 0402 3688.87,1499.91 r90 bottom value=0.1uF
C17 "GRM155R71E104KE14D" 0402 4190.85,1013.32 r0 bottom value=0.1uF
C18 "GRM155R71E104KE14D" 0402 4186.18,1254.06 r0 bottom value=0.1uF
C19 "GRM033C80J105ME05D" FP-GRM033C80J105ME05D_0201-MFG 3956.58,1193.07 r90 bottom value=1µF
C20 "GRM033C80J105ME05D" FP-GRM033C80J105ME05D_0201-MFG 3445.84,994.56 r90 bottom value=1µF
C21 "GRM033C80J105ME05D" FP-GRM033C80J105ME05D_0201-MFG 3443.33,1355.85 r270 bottom value=1µF
C22 "GRM033C80J105ME05D" FP-GRM033C80J105ME05D_0201-MFG 3916.09,1115.08 r0 bottom value=1µF
C23 "CL10A335KP8NNNC" FP-CL10A335KP8NNNC_0603-MFG 4107.94,624.92 r0 bottom value=3.3µF
C24 "GRM155R71E104KE14D" 0402 4100.96,554.26 r0 bottom value=0.1uF
C25 "CL10A335KP8NNNC" FP-CL10A335KP8NNNC_0603-MFG 3875,540.45 r180 bottom value=3.3µF
C26 "GRM155R71E104KE14D" 0402 3875.31,608.97 r180 bottom value=0.1uF
C27 "GRM155R71E104KE14D" 0402 3875.31,658.97 r180 bottom value=0.1uF
C28 "GRM155R71E104KE14D" 0402 3875.31,708.97 r180 bottom value=0.1uF
C29 "GRM033C80J105ME05D" FP-GRM033C80J105ME05D_0201-MFG 3445.84,1108.91 r270 bottom value=1µF
C30 "GRM033C80J105ME05D" FP-GRM033C80J105ME05D_0201-MFG 3815,1273.75 r180 bottom value=1µF
C31 "GRM033C80J105ME05D" FP-GRM033C80J105ME05D_0201-MFG 3814.85,1239.57 r180 bottom value=1µF
C32 "GRM033C80J105ME05D" FP-GRM033C80J105ME05D_0201-MFG 3445.84,1234.32 r90 bottom value=1µF
C33 "GRM188Z71A475ME15D" 0603 3738.88,569.08 r0 bottom value=4.7uF
C34 "GRM155R71E104KE14D" 0402 3736.38,658.97 r0 bottom value=0.1uF
C35 "GRM155R71E104KE14D" 0402 4139.44,717.13 r270 bottom value=0.1uF
C36 "GRM155R71E104KE14D" 0402 3736.38,708.97 r0 bottom value=0.1uF
C37 "GRM155R71E104KE14D" 0402 3739.61,493 r0 bottom value=0.1uF
C38 "GRM155R71E104KE14D" 0402 3531.39,509.65 r90 bottom value=0.1uF
C39 "GRM033C80J105ME05D" FP-GRM033C80J105ME05D_0201-MFG 3956.58,973 r90 bottom value=1µF
C40 "GRM033C80J105ME05D" FP-GRM033C80J105ME05D_0201-MFG 3395.84,1108.91 r270 bottom value=1µF
C41 "GRM033C80J105ME05D" FP-GRM033C80J105ME05D_0201-MFG 3673,1193.07 r90 bottom value=1µF
C42 "GRM033C80J105ME05D" FP-GRM033C80J105ME05D_0201-MFG 3412.37,1355.85 r270 bottom value=1µF
C43 "GRM155R71E104KE14D" 0402 5975,914.8 r180 top value=0.1uF
C44 "GRM033C80J105ME05D" FP-GRM033C80J105ME05D_0201-MFG 3395.84,1234.06 r90 bottom value=1µF
C45 "GRM033C80J105ME05D" FP-GRM033C80J105ME05D_0201-MFG 3395.84,994.56 r90 bottom value=1µF
C46 "GRM033C80J105ME05D" FP-GRM033C80J105ME05D_0201-MFG 3693.17,1115.1 r270 bottom value=1µF
C47 "GRM033C80J105ME05D" FP-GRM033C80J105ME05D_0201-MFG 3956.58,1060.9 r90 bottom value=1µF
C48 "GRM155R71E104KE14D" 0402 3287.47,633.24 r270 top value=0.1uF
C49 "GRM033Z71C104KE14D" 0201 3477,1360 r90 bottom value=0.1uF
C50 "GRM033Z71C104KE14D" 0201 3814.85,946.1 r90 bottom value=0.1uF
C51 "GRM033Z71C104KE14D" 0201 3892.96,1257.37 r0 bottom value=0.1uF
C52 "CL10A335KP8NNNC" FP-CL10A335KP8NNNC_0603-MFG 3310.82,1114.16 r90 bottom value=3.3µF
C53 "CL10A335KP8NNNC" FP-CL10A335KP8NNNC_0603-MFG 3274.66,1362.64 r90 bottom value=3.3µF
C54 "GRM033Z71C104KE14D" 0201 3654.78,1115.1 r90 bottom value=0.1uF
C55 "GRM033Z71C104KE14D" 0201 3992.66,1115.08 r180 bottom value=0.1uF
C56 "GRM033Z71C104KE14D" 0201 3673,1004.38 r90 bottom value=0.1uF
C57 "GRM155R71E104KE14D" 0402 2162.4,1279.45 r180 top value=0.1uF
C58 "GJM1555C1H120JB01D" FP-GJM1555C1H120JB01D_0402-MFG 3356.21,748.05 r90 top value=12pF
C59 "GJM1555C1H120JB01D" FP-GJM1555C1H120JB01D_0402-MFG 3355,812.47 r90 top value=12pF
C60 "GRM155R71E104KE14D" 0402 3215,418.33 r0 top value=0.1uF
C61 "GRM155R71E104KE14D" 0402 3653.69,81.97 r90 bottom value=0.1uF
C62 "GRM155R71E104KE14D" 0402 3713.69,81.97 r90 bottom value=0.1uF
C63 "GRM1555C1E103JE01D" FP-GRM1555C1E103JE01D_0402-MFG 2207.84,767.39 r270 top value=10nF
C64 "GRM155R71E104KE14D" 0402 2017.57,746.48 r270 top value=0.1uF
C65 "GRM155R71E104KE14D" 0402 1939.22,1024.86 r0 top value=0.1uF
C66 "885012105010" 0402 2800.7,1120.06 r90 bottom value=0.1uF
C67 "GRM188Z71C475KE21D" 0603 611.03,672.69 r90 top value=4.7uF
C68 "CL10A335KP8NNNC" FP-CL10A335KP8NNNC_0603-MFG 924.76,669.66 r90 top value=3.3µF
C69 "GRM155R71E104KE14D" 0402 862.1,661.79 r90 top value=0.1uF
C70 "GRM155R71E104KE14D" 0402 1974.81,1395.84 r180 bottom value=0.1uF
C71 "GRM155R71E104KE14D" 0402 587.8,785.43 r180 bottom value=0.1uF
C72 "GRM1555C1H331JA01D" 0402 1745,571.95 r90 top value=330pF
C73 "GRM1555C1H331JA01D" 0402 1805,571.95 r90 top value=330pF
C74 "GRM1555C1H331JA01D" 0402 1865,571.95 r90 top value=330pF
C75 "GRM1555C1H331JA01D" 0402 1924,571.95 r90 top value=330pF
C76 "GRM188Z71A475ME15D" 0603 3713.17,668.93 r270 top value=4.7uF
C77 "GRM188Z71A475ME15D" 0603 3861.33,668.93 r270 top value=4.7uF
C78 "GRM155R71E104KE14D" 0402 3720.36,789.94 r0 bottom value=0.1uF
C79 "GRM155R71E104KE14D" 0402 3844.81,789.94 r0 bottom value=0.1uF
C80 "GRM155R71E104KE14D" 0402 3948.62,789.94 r180 bottom value=0.1uF
C81 "GRM1555C1H331JA01D" 0402 2090,572.47 r90 top value=330pF
C82 "GRM1555C1H331JA01D" 0402 2150,572.47 r90 top value=330pF
C83 "GRM1555C1H331JA01D" 0402 2210,572.47 r90 top value=330pF
C84 "GRM1555C1H331JA01D" 0402 2269,572.47 r90 top value=330pF
C85 "GRM1555C1H331JA01D" 0402 4747.11,585.15 r90 top value=330pF
C86 "GRM1555C1H331JA01D" 0402 4802.11,585.15 r90 top value=330pF
C87 "GRM1555C1H331JA01D" 0402 4856.7,585.15 r90 top value=330pF
C88 "GRM1555C1H331JA01D" 0402 4911.11,585.15 r90 top value=330pF
C89 "GRM188Z71A475ME15D" 0603 3015,660 r90 bottom value=4.7uF
C90 "GRM155R71E104KE14D" 0402 3595,594.91 r270 bottom value=0.1uF
C91 "GRM155R71E104KE14D" 0402 3590,595 r270 top value=0.1uF
C92 "GRM1555C1H331JA01D" 0402 4965,586 r90 top value=330pF
C93 "GRM1555C1H331JA01D" 0402 5017.97,585.3 r90 top value=330pF
C94 "GRM1555C1H331JA01D" 0402 5073,585.3 r90 top value=330pF
C95 "GRM1555C1H331JA01D" 0402 5128.54,585.3 r90 top value=330pF
C96 "GRM1555C1H331JA01D" 0402 4339.72,549.93 r90 top value=330pF
C97 "GRM1555C1H331JA01D" 0402 2010,571.38 r90 top value=330pF
C98 "GRM155R71E104KE14D" 0402 3494.98,1177.95 r180 bottom value=0.1uF
C99 "GRM155R71E104KE14D" 0402 5570,487.03 r180 bottom value=0.1uF
C100 "GRM155R71E104KE14D" 0402 4735,1152.06 r0 bottom value=0.1uF
C101 "GRM188R72A104KA35D" 0603 420.79,454.11 r180 top value=0.1uF
C102 "GRM32EC72A106KE05L" FP-GRM32EC72A106KE05L_1210-MFG 1160.42,558.6 r270 top
C103 "GRM188R72A104KA35J" 0603 1269.1,548.98 r90 top value=0.1uF
C104 "GRM32EC72A106KE05L" FP-GRM32EC72A106KE05L_1210-MFG 1375.6,579.93 r270 top
C105 "GRM32EC72A106KE05L" FP-GRM32EC72A106KE05L_1210-MFG 1488.89,593.27 r270 bottom
C106 "GRM188R72A104KA35D" 0603 1579.67,844.07 r90 top value=0.1uF
C107 "GRM32EC72A106KE05L" FP-GRM32EC72A106KE05L_1210-MFG 1757.45,759.21 r270 bottom
C108 "GRM188R72A104KA35D" 0603 1771.58,840.73 r90 top value=0.1uF
C109 "GRM1555C1H102JA01D" 0402 1771.58,710 r270 top value=1000pF
C110 "GRM188R72A104KA35D" 0603 740,493.54 r90 top value=0.1uF
C111 "GRM155R71E104KE14D" 0402 5009,992.82 r0 top value=0.1uF
C112 "GJM1555C1H120JB01D" FP-GJM1555C1H120JB01D_0402-MFG 6730.7,390.77 r270 bottom value=12pF
C113 "GJM1555C1H120JB01D" FP-GJM1555C1H120JB01D_0402-MFG 6733.44,477.16 r270 bottom value=12pF
C114 "GRM188Z71A106MA73D" 0603 6279,1343.28 r90 top value=10uF
C115 "GRM1555C1E103JE01D" FP-GRM1555C1E103JE01D_0402-MFG 6344,1343.46 r270 top value=10nF
C116 "GRM155R70J105MA12D" 0402 6556.28,941.71 r90 top value=1uF
C117 "GRM155R71E104KE14D" 0402 6556.28,945.08 r90 bottom value=0.1uF
C118 "GRM155R70J105MA12D" 0402 6493.94,745.04 r0 top value=1uF
C119 "GRM155R71E104KE14D" 0402 6374.14,745.04 r180 top value=0.1uF
C120 "GRM155R70J105MA12D" 0402 6755.41,729.88 r180 top value=1uF
C121 "GRM155R71E104KE14D" 0402 6870.21,729.88 r0 bottom value=0.1uF
C122 "GRM188Z71A106MA73D" 0603 6210,1003.65 r90 top value=10uF
C123 "GRM1555C1E103JE01D" FP-GRM1555C1E103JE01D_0402-MFG 6280.09,987.15 r270 top value=10nF
C124 "GRM155R70J105MA12D" 0402 6755.41,670.83 r180 top value=1uF
C125 "GRM155R71E104KE14D" 0402 6870.21,670.83 r0 bottom value=0.1uF
C126 "GRM155R70J105MA12D" 0402 6755.41,788.94 r180 top value=1uF
C127 "GRM155R71E104KE14D" 0402 6870.21,788.94 r0 bottom value=0.1uF
C128 "GRM188Z71A106MA73D" 0603 6351.36,621.24 r180 bottom value=10uF
C129 "GRM1555C1E103JE01D" FP-GRM1555C1E103JE01D_0402-MFG 6355.51,681.97 r0 bottom value=10nF
C130 "GRM155R70J105MA12D" 0402 6625,622.13 r90 top value=1uF
C131 "GRM155R71E104KE14D" 0402 6670,495 r270 bottom value=0.1uF
C132 "GRM155R70J105MA12D" 0402 6493.94,695.04 r0 top value=1uF
C133 "GRM155R71E104KE14D" 0402 6379.14,695.04 r180 top value=0.1uF
C134 "GRM155R71E104KE14D" 0402 1205.5,974.22 r180 bottom value=0.1uF
C135 "GRM1555C1E103JE01D" FP-GRM1555C1E103JE01D_0402-MFG 325,1105.38 r90 bottom value=10nF
C136 "GRM155R71E104KE14D" 0402 1607.87,1117.23 r180 top value=0.1uF
C137 "GRM155R71E104KE14D" 0402 1607.87,1340 r180 top value=0.1uF
C138 "GRM155R71E104KE14D" 0402 1603.77,1753.19 r180 top value=0.1uF
C139 "GRM155R71E104KE14D" 0402 1193.04,1165.27 r0 top value=0.1uF
C140 "GRM155R71E104KE14D" 0402 1200.59,1376.28 r0 top value=0.1uF
C141 "GRM155R71E104KE14D" 0402 1194.14,1733.64 r0 top value=0.1uF
C142 "GRM155R71E104KE14D" 0402 1191.36,1554.93 r0 bottom value=0.1uF
C143 "GJM1555C1H8R0DB01D" FP-GJM1555C1H8R0DB01D_0402-MFG 1193.21,1143.27 r270 bottom value=8pF
C144 "GJM1555C1H8R0DB01D" FP-GJM1555C1H8R0DB01D_0402-MFG 1193.07,1256.29 r90 bottom value=8pF
C145 "GRM155R71E104KE14D" 0402 495.31,1188.47 r0 top value=0.1uF
C146 "GRM155C71A105KE11D" FP-GRM155C71A105KE11D_0402-MFG 954.01,942.22 r180 bottom value=1µF
C147 "GRM155R71E104KE14D" 0402 787.63,1021.22 r90 top value=0.1uF
C148 "GRM155C71A105KE11D" FP-GRM155C71A105KE11D_0402-MFG 848.81,1517.94 r270 top value=1µF
C149 "GRM1555C1E103JE01D" FP-GRM1555C1E103JE01D_0402-MFG 1098.65,1359.8 r90 top value=10nF
C150 "GRM155R71E104KE14D" 0402 480.5,1505.66 r0 top value=0.1uF
C151 "GRM155R71E104KE14D" 0402 360.82,1225.67 r270 bottom value=0.1uF
C152 "GRM1555C1E103JE01D" FP-GRM1555C1E103JE01D_0402-MFG 415.82,1225.67 r90 bottom value=10nF
C153 "GRM155C81C225KE11D" 0402 1105,1221.57 r180 top value=2.2uF
C154 "GRM155R71E104KE14D" 0402 774.98,941.85 r180 bottom value=0.1uF
C155 "GRM155R71E104KE14D" 0402 740.38,1021.22 r270 top value=0.1uF
C156 "GRM155C71A105KE11D" FP-GRM155C71A105KE11D_0402-MFG 1105,1270 r180 top value=1µF
C157 "GRM21BZ71A226ME15L" 0805_HV 2387.33,1061.68 r180 top value=22uF
C158 "GRM21BZ71A226ME15L" 0805_HV 2387.33,1151.68 r180 top value=22uF
C159 "GRM32ER71A476ME15L" 1210_270 2370.42,1126.68 r180 bottom value=47uF
C160 "GRM188R71E474KA12D" 0603 2322.84,801.68 r270 top value=0.47uF
C161 "GRM188Z71C475KE21D" 0603 5664.06,1227.1 r90 bottom value=4.7uF
C162 "GRM155C71A105KE11D" FP-GRM155C71A105KE11D_0402-MFG 5635.58,1227.04 r270 top value=1µF
C163 "GRM155R71E104KE14D" 0402 5695.21,1222.1 r90 top value=0.1uF
C164 "GRM32EC72A106KE05L" FP-GRM32EC72A106KE05L_1210-MFG 6004.13,1223.43 r270 top
C165 "GRM155R71E104KE14D" 0402 5909.13,1222.1 r90 top value=0.1uF
C166 "GCM155R72A272KA37D" FP-GCM155R72A272KA37D_0402-MFG 5854.25,1128.43 r270 bottom value=2.7nF
C167 "GRM32EC72A106KE05L" FP-GRM32EC72A106KE05L_1210-MFG 2242.33,966.68 r270 top
C168 "GRM32EC72A106KE05L" FP-GRM32EC72A106KE05L_1210-MFG 2242.33,966.68 r270 bottom
C169 "GRM21BZ71A226ME15L" 0805_HV 2842.02,1584.28 r180 top value=22uF
C170 "GRM21BZ71A226ME15L" 0805_HV 2841.41,1673.07 r180 top value=22uF
C171 "GRM32ER71A476ME15L" 1210_270 2821.87,1696.91 r180 bottom value=47uF
C172 "GRM188Z71C475KE21D" 0603 5664.13,1646.29 r90 bottom value=4.7uF
C173 "GRM155C71A105KE11D" FP-GRM155C71A105KE11D_0402-MFG 5635.58,1643.07 r270 top value=1µF
C174 "GRM155R71E104KE14D" 0402 5695.21,1643.29 r90 top value=0.1uF
C175 "GRM32EC72A106KE05L" FP-GRM32EC72A106KE05L_1210-MFG 6004.13,1642.62 r270 top
C176 "GRM155R71E104KE14D" 0402 5909.13,1641.29 r90 top value=0.1uF
C177 "GRM188R71E474KA12D" 0603 2745.09,1338.05 r180 top value=0.47uF
C178 "GCM155R72A272KA37D" FP-GCM155R72A272KA37D_0402-MFG 5854.25,1547.62 r270 bottom value=2.7nF
C179 "GRM32EC72A106KE05L" FP-GRM32EC72A106KE05L_1210-MFG 2663.88,1600.34 r270 bottom
C180 "GRM32EC72A106KE05L" FP-GRM32EC72A106KE05L_1210-MFG 2694,1499.3 r270 top
C181 "GRM155R71E104KE14D" 0402 657.31,2065 r180 top value=0.1uF
C182 "GRM155R71E104KE14D" 0402 766.92,2037.31 r90 top value=0.1uF
C183 "GRM155R71E104KE14D" 0402 522.55,1944.88 r0 bottom value=0.1uF
C184 "GRM155R71E104KE14D" 0402 522.55,1997.05 r0 bottom value=0.1uF
C185 "GRM21BZ71A226ME15L" 0805_HV 2872,387 r180 top value=22uF
C186 "GRM155R71E104KE14D" 0402 2872,314 r180 top value=0.1uF
C187 "GRM155C71A105KE11D" FP-GRM155C71A105KE11D_0402-MFG 2700.34,267.42 r270 top value=1µF
C188 "GRM155R71E104KE14D" 0402 2760.42,264.96 r90 top value=0.1uF
C189 "GJM1555C1H120JB01D" FP-GJM1555C1H120JB01D_0402-MFG 6541.38,1370 r0 bottom value=12pF
C190 "GJM1555C1H120JB01D" FP-GJM1555C1H120JB01D_0402-MFG 6640.35,1370.13 r180 bottom value=12pF
C191 "GRM188Z71A106MA73D" 0603 6279,1485.21 r90 top value=10uF
C192 "GRM1555C1E103JE01D" FP-GRM1555C1E103JE01D_0402-MFG 6344,1481.27 r270 top value=10nF
C193 "GRM155R70J105MA12D" 0402 6556.28,1891.71 r90 top value=1uF
C194 "GRM155R71E104KE14D" 0402 6556.28,1895.08 r90 bottom value=0.1uF
C195 "GRM155R70J105MA12D" 0402 6498.94,1695.04 r0 top value=1uF
C196 "GRM155R71E104KE14D" 0402 6379.14,1695.04 r180 top value=0.1uF
C197 "GRM155R70J105MA12D" 0402 6751.41,1679.88 r180 top value=1uF
C198 "GRM155R71E104KE14D" 0402 6870.21,1679.88 r0 bottom value=0.1uF
C199 "GRM188Z71A106MA73D" 0603 6278.93,1156.97 r270 top value=10uF
C200 "GRM1555C1E103JE01D" FP-GRM1555C1E103JE01D_0402-MFG 6334.77,1155 r90 top value=10nF
C201 "GRM155R70J105MA12D" 0402 6755.41,1620.83 r180 top value=1uF
C202 "GRM155R71E104KE14D" 0402 6870.21,1620.83 r0 bottom value=0.1uF
C203 "GRM155R70J105MA12D" 0402 6751.41,1738.94 r180 top value=1uF
C204 "GRM155R71E104KE14D" 0402 6870.21,1738.94 r0 bottom value=0.1uF
C205 "GRM188Z71A106MA73D" 0603 6351.36,1571.24 r180 bottom value=10uF
C206 "GRM1555C1E103JE01D" FP-GRM1555C1E103JE01D_0402-MFG 6355.51,1631.97 r0 bottom value=10nF
C207 "GRM155R70J105MA12D" 0402 6625,1570.47 r90 top value=1uF
C208 "GRM155R71E104KE14D" 0402 6670,1445 r270 bottom value=0.1uF
C209 "GRM155R70J105MA12D" 0402 6498.94,1645.04 r0 top value=1uF
C210 "GRM155R71E104KE14D" 0402 6379.14,1645.04 r180 top value=0.1uF
C211 "GRM188R72A104KA35D" 0603 5880,230 r90 bottom value=0.1uF
C212 "GRM188R72A104KA35D" 0603 5880,480 r90 bottom value=0.1uF
C213 "GRM188R72A104KA35D" 0603 3890,2005 r270 bottom value=0.1uF
C214 "GRM1885C1H102JA01D" 0603 6199.18,230 r90 bottom value=1000pF
C215 "GQM1875C2E101JB12D" FP-GQM1875C2E101JB12D_0603-MFG 6124.18,230 r270 bottom value=100pF
C216 "GRM1885C1H102JA01D" 0603 6000,230 r90 bottom value=1000pF
C217 "GRM1885C1H102JA01D" 0603 6199.18,480 r90 bottom value=1000pF
C218 "GQM1875C2E101JB12D" FP-GQM1875C2E101JB12D_0603-MFG 6124.18,480 r270 bottom value=100pF
C219 "GRM1885C1H102JA01D" 0603 6000,480 r90 bottom value=1000pF
C220 "GRM1885C1H102JA01D" 0603 6492.17,290.82 r0 bottom value=1000pF
C221 "GRM1885C1H102JA01D" 0603 6197.13,494.67 r180 top value=1000pF
C222 "GRM155R71H472KA01D" 0402 6940,265 r90 top value=4700pF
C223 "GRM155R71E104KE14D" 0402 5483.66,140.04 r90 bottom value=0.1uF
C224 "GRM188R72A104KA35D" 0603 5642.05,93.47 r180 bottom value=0.1uF
C225 "GRM155R71E104KE14D" 0402 7182.8,136.46 r270 bottom value=0.1uF
C226 "GRM155R71E104KE14D" 0402 7010,60.4 r180 top value=0.1uF
C227 "GRM21BZ71E106KE15L" 0805_HV 285,906.68 r0 bottom value=10uF
C228 "GJM1555C1H150FB01D" FP-GJM1555C1H150FB01D_0402-MFG 658.65,1124.76 r0 top value=15pF
C229 "GR442QR73D102KW01L" 1808 731.46,180.12 r0 top value=1000pF
C230 "GR442QR73D102KW01L" 1808 227.89,1373.06 r270 bottom value=1000pF
C231 "GRM155C81C225KE11D" 0402 352.83,962.27 r90 top value=2.2uF
C232 "GRM155C71A105KE11D" FP-GRM155C71A105KE11D_0402-MFG 660,1040.15 r270 top value=1µF
C233 "GRM155R71E104KE14D" 0402 577.56,962.27 r270 top value=0.1uF
C234 "GR442QR73D102KW01L" 1808 1398.86,1025 r0 bottom value=1000pF
C235 "GR442QR73D102KW01L" 1808 7235,1115 r0 top value=1000pF
C236 "CL10A335KP8NNNC" FP-CL10A335KP8NNNC_0603-MFG 2255.95,1423.5 r270 top value=3.3µF
C237 "GRM155R71E104KE14D" 0402 2195.94,1431.38 r270 top value=0.1uF
C238 "GRM155R71E104KE14D" 0402 5376.11,1209.78 r270 top value=0.1uF
C239 "GRM155R71E104KE14D" 0402 5339.88,764.77 r90 top value=0.1uF
C240 "GRM155R71E104KE14D" 0402 4670.38,1236.85 r90 top value=0.1uF
C241 "GRM155R71E104KE14D" 0402 4636.65,1588.39 r90 top value=0.1uF
C242 "GRM155R71E104KE14D" 0402 5036.38,1451.95 r180 top value=0.1uF
C243 "GRM155R71E104KE14D" 0402 4495.23,625.31 r90 bottom value=0.1uF
C244 "GRM155R71E104KE14D" 0402 4635,540.45 r270 bottom value=0.1uF
C245 "GRM155R71E104KE14D" 0402 4715,841.18 r270 top value=0.1uF
C246 "GRM155R71E104KE14D" 0402 4640,1712.48 r180 top value=0.1uF
C247 "GR442QR73D102KW01L" 1808 7185.15,2106.97 r0 top value=1000pF
C248 "GRM188R72A104KA35D" 0603 6053.19,701.15 r180 top value=0.1uF
C249 "GRM188R72A104KA35D" 0603 856.86,425.41 r0 top value=0.1uF
C250 "GRM155R71E104KE14D" 0402 283.47,1506.27 r0 top value=0.1uF
C251 "GRM155R71E104KE14D" 0402 1197.04,1367.79 r90 bottom value=0.1uF
C252 "GRM155R71E104KE14D" 0402 1508.47,1266.6 r270 bottom value=0.1uF
C253 "GRM155R71H104KE14D" FP-GRM155R71H104KE14D_0402-MFG 2953.5,1632.38 r90 bottom value=100nF
C254 "KGM05CR51A106MH" FP-KGM05CR51A106MH_0402-MFG 3004.7,1619.91 r270 bottom value=10µF
C255 "GRM155R71H104KE14D" FP-GRM155R71H104KE14D_0402-MFG 3148.3,1684.38 r0 bottom value=100nF
C256 "GRM155R61E225KE11D" 0402_070 3148.3,1727.09 r180 bottom value=2.2uF
C257 "GRM155R71E104KE14D" 0402 3617.11,851 r180 bottom value=0.1uF
C258 "KGM05CR51A106MH" FP-KGM05CR51A106MH_0402-MFG 2754.67,1120.32 r90 bottom value=10µF
C259 "885012105010" 0402 2870.35,828.59 r270 bottom value=0.1uF
C260 "885012105010" 0402 2662.59,404.5 r0 top value=0.1uF
C261 "KGM05CR51A106MH" FP-KGM05CR51A106MH_0402-MFG 2615.34,354.8 r180 top value=10µF
C262 "GRM155R71E104KE14D" 0402 168.23,1971.27 r180 top value=0.1uF
C263 "885012105010" 0402 6589.21,2013.14 r270 bottom value=0.1uF
C264 "885012105010" 0402 2338.77,1551.57 r270 top value=0.1uF
C265 "KGM05CR51A106MH" FP-KGM05CR51A106MH_0402-MFG 2274.78,1550.65 r270 top value=10µF
C266 "C1005X6S1C105K050BC" 0402 2664.95,1820.24 r0 bottom value=1uF
C267 "885012105010" 0402 2033.53,1577 r0 bottom value=0.1uF
C268 "885012105010" 0402 2389,548.03 r180 bottom value=0.1uF
C269 "KGM05CR51A106MH" FP-KGM05CR51A106MH_0402-MFG 2389,642.68 r180 bottom value=10µF
C270 "885012105010" 0402 6777.35,1305.89 r180 bottom value=0.1uF
C271 "885012105010" 0402 2862.46,1097.32 r90 bottom value=0.1uF
C272 "885012105010" 0402 2667.72,1107.14 r270 bottom value=0.1uF
D1 "SMBJ6.5CA" SMB-Bi 1049.65,505.45 r0 bottom value=6.5V
D2 "150060VS75000" WL-SMCW_GREEN 1810.94,1018.81 r270 top value=Green
D3 "150060VS75000" WL-SMCW_GREEN 178.78,1584.03 r90 top value=Green
D4 "150060VS75000" WL-SMCW_GREEN 2526.43,2208.3 r90 top value=Green
D5 "150060VS75000" WL-SMCW_GREEN 2036.27,91.9 r270 top value=Green
D6 "150060VS75000" WL-SMCW_GREEN 2868.49,47.06 r0 top value=Green
D7 "150060VS75000" WL-SMCW_GREEN 2421.16,2208.3 r90 top value=Green
D8 "150060VS75000" WL-SMCW_GREEN 2312.35,2208.3 r90 top value=Green
D9 "150060VS75000" WL-SMCW_GREEN 2200.52,2208.3 r90 top value=Green
D10 "150060VS75000" WL-SMCW_GREEN 2088.59,2208.3 r90 top value=Green
D11 "150060VS75000" WL-SMCW_GREEN 1980.11,2208.3 r90 top value=Green
D12 "150060VS75000" WL-SMCW_GREEN 1870.7,2208.3 r90 top value=Green
D13 "150060VS75000" WL-SMCW_GREEN 1753.16,2208.3 r90 top value=Green
D14 "150060VS75000" WL-SMCW_GREEN 1642.17,2208.3 r90 top value=Green
D15 "TPD1E01B04DPYR" DPY0002A 4351.58,466.66 r180 top
D16 "TPD1E01B04DPYR" DPY0002A 1997.72,485.1 r180 top
Designator2 "Comment" BRAKE_WAY_HOLES1X3 1848.57,-39.37 r0 top
Designator2_1 "Comment" BRAKE_WAY_HOLES1X3 1848.57,2620.63 r0 top
Designator3 "Comment" BRAKE_WAY_HOLES1X3 184.09,-39.37 r0 top
Designator4 "Comment" BRAKE_WAY_HOLES1X3 4372.53,-40.63 r0 top
Designator4_1 "Comment" BRAKE_WAY_HOLES1X3 4372.53,2619.37 r0 top
Designator5 "Comment" BRAKE_WAY_HOLES1X3 7494.59,-39.37 r0 top
Designator6 "Comment" BRAKE_WAY_HOLES1X3 218.32,2340.63 r180 top
Designator7 "Comment" BRAKE_WAY_HOLES1X3 3496.1,2339.37 r180 top
Designator7_1 "Comment" BRAKE_WAY_HOLES1X3 3496.1,4999.37 r180 top
Designator8 "Comment" BRAKE_WAY_HOLES1X3 5807.39,2340.63 r180 top
Designator9 "Comment" BRAKE_WAY_HOLES1X3 7469.96,2339.37 r180 top
Designator9_1 "Comment" BRAKE_WAY_HOLES1X3 7469.96,4999.37 r180 top
Designator10 "Comment" BRAKE_WAY_HOLES1X3 184.09,2620.63 r0 top
Designator11 "Comment" BRAKE_WAY_HOLES1X3 217.32,5000.63 r180 top
Designator12 "Comment" BRAKE_WAY_HOLES1X3 5806.39,5000.63 r180 top
Designator13 "Comment" BRAKE_WAY_HOLES1X3 7494.59,2620.63 r0 top
DS1 "150060RS75000" WL-SMCW_RED 2739.41,1781.37 r180 top value=Red
DS2 "150060RS75000" WL-SMCW_RED 2698.87,47.97 r180 top value=Red
DS3 "150060RS75000" WL-SMCW_RED 115.08,1583.47 r90 top value=Red
DS4 "150060RS75000" WL-SMCW_RED 838.68,304.16 r270 top value=Red
FB1 "BLM18EG121SN1D" FP-BLM18EG121SN1D_0603-MFG 4000.08,564.71 r180 bottom
FB2 "BLM18EG121SN1D" FP-BLM18EG121SN1D_0603-MFG 3621.02,485 r180 bottom
FB3 "BLM18EG121SN1D" FP-BLM18EG121SN1D_0603-MFG 6188.68,1310.55 r0 top
FB4 "BLM18EG121SN1D" FP-BLM18EG121SN1D_0603-MFG 6115.92,970.9 r0 top
FB5 "BLM18EG121SN1D" FP-BLM18EG121SN1D_0603-MFG 6188.68,1449.44 r0 top
FB6 "BLM18EG121SN1D" FP-BLM18EG121SN1D_0603-MFG 6188.68,1188.64 r0 top
FID1 "Fiducial" Fiducial10-20 6995.38,2165 r90 top
FID2 "Fiducial" Fiducial10-20 113.79,392.07 r90 top
FID3 "Fiducial" Fiducial10-20 113.79,1771.83 r90 top
FID4 "Fiducial" Fiducial10-20 6995.38,2165 r90 bottom
FID5 "Fiducial" Fiducial10-20 113.79,392.07 r90 bottom
FID6 "Fiducial" Fiducial10-20 113.79,1771.83 r90 bottom
FID7 "Fiducial" Fiducial10-20 400,-180 r90 top
FID8 "Fiducial" Fiducial10-20 7300,-180 r270 top
FID9 "Fiducial" Fiducial10-20 7299,5140 r270 top
FID10 "Fiducial" Fiducial10-20 7299,5140 r90 bottom
FID11 "Fiducial" Fiducial10-20 7300,-180 r90 bottom
FID12 "Fiducial" Fiducial10-20 400,-180 r270 bottom
J1 "PBC02SAAN" Sullins_PBC02SAAN 1395.54,1975 r180 top locked
J1/J3 "SSQ-110-03-T-D" BoosterPack_40pin_J1J3 2054.17,300 r270 bottom locked
J2 "DM3BT-DSF-PEJS" Hirose_DM3BT-DSF-PEJS 570,362.52 r180 bottom locked
J2/J4 "SSQ-110-03-T-D" BoosterPack_40pin_J2J4 2054.17,2000 r270 bottom locked
J5 "2012670005" FP-2012670005_CONN_USB_9MM39_8MM21-MFG 1118.35,154.53 r0 top locked
J5/J7 "SSQ-110-03-T-D" BoosterPack_40pin_J5J7 4554.17,300 r270 bottom
J6 "FH12A-40S-0.5SH(55)" FP-FH12A-40S-0.5SH(55)_FFC40-MFG 945.63,2200 r180 bottom locked
J6/J8 "SSQ-110-03-T-D" BoosterPack_40pin_J6J8 4554.17,2000 r270 bottom locked
J7 "LPJG16314A4NL" FP-LPJG16314A4NL_CONN_RJ45-MFG 7444,655 r90 top locked
J8 "LPJG16314A4NL" FP-LPJG16314A4NL_CONN_RJ45-MFG 7444,1645 r90 top locked
J9 "PBC02SAAN" Sullins_PBC02SAAN 1445,136.05 r180 top
J10 "PBC02SAAN" Sullins_PBC02SAAN 1445,360 r0 top
J11 "PBC03SAAN" PBC03SAAN 5304.17,250 r180 top locked
J12 "PBC03SAAN" PBC03SAAN 5304.17,2050 r180 top locked
J13 "PBC02SAAN" Sullins_PBC02SAAN 5235.83,543.25 r0 top
J14 "PBC02SAAN" Sullins_PBC02SAAN 5367.11,543.25 r0 top
J15 "PBC02SAAN" Sullins_PBC02SAAN 6327.06,165 r180 top
J16 "PBC02SAAN" Sullins_PBC02SAAN 6327.06,415 r180 top
J17 "PBC02SAAN" Sullins_PBC02SAAN 1668.62,1023.77 r90 top
J18 "PBC02SAAN" Sullins_PBC02SAAN 2796.34,491.93 r90 top
J23 "PRPC005DAAN-RC" Sullins_xxPC005DAAN-RC 3604.17,2000 r90 top locked
J24 "PEC05SAAN" Sullins_PxC05SAAN 5999.18,115 r180 top locked
J25 "PEC05SAAN" Sullins_PxC05SAAN 5999.18,365 r180 top locked
J33 "OSTTE030161" On-Shore_OSTTE030161 6654.17,183.86 r0 top locked
J34 "1051640001" Molex_1051640001 0,1044.08 r270 top
L1 "BLM21PG300SN1D" FP-BLM21PG300SN1D_0805-MFG 1309.67,435.62 r0 top
L2 "74438356022" WE-MAPI_4020 2555.75,1000.74 r90 top value=2.2uH
L3 "74438356022" WE-MAPI_4020 3003.77,1508.9 r90 top value=2.2uH
L4 "74405020100" FP-74405020100_SMT_IND_2MM0_1MM6-MFG 2968.49,266.14 r90 top
LBL1 "THT-14-423-10" Label_650x200 6610,2187.06 r0 top
Logo1 "CE Mark" CE_Mark_5mm 564.56,1375.69 r0 top
Logo2 "Texas Instruments" TI_Stacked_Overlay_Small 5135,1778.31 r0 top locked
Logo3 "FCC disclaimer" FCC_disclaimer 9836.36,4289 r270 bottom
Logo4 "WEEE logo" WEEE_Minimum 6005,838.02 r180 bottom
Q1 "IRLML6401TRPBF" SOT-23 795.63,1904.12 r180 bottom value=-12V
Q2 "IRLML6401TRPBF" SOT-23 1021,2038 r0 top value=-12V
Q3 "IRLML6401TRPBF" SOT-23 1163.12,2088.08 r270 top value=-12V
Q4 "BSS123" SOT-23 7274.1,1140 r270 bottom value=100V
Q5 "BSS123" SOT-23 7324,113.66 r90 top value=100V
Q6 "BSS123" SOT-23 7324,113.66 r90 bottom value=100V
Q7 "BSS123" SOT-23 7340,2165 r270 bottom value=100V
Q8 "BSS123" SOT-23 7433.87,1140.67 r90 bottom value=100V
Q9 "BSS123" SOT-23 7580.33,1139.39 r90 bottom value=100V
Q10 "BSS223PWH6327" SOT-323 2859.06,1852.03 r270 top value=-20V
Q11 "BSS123W-7-F" SOT-323 2692.53,120.9 r0 top value=100V
Q13 "BSS123W-7-F" SOT-323 1930,123.39 r0 top value=100V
